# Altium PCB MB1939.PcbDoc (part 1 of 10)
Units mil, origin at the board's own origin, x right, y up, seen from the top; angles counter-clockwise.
Board outline 5910.64 x 4335.93 mil, 6 copper layers (Top Layer, l2_GND, L3_SIG, L4_VCC, L5_GND, Bottom Layer), stack 58.424 mil thick; 635 components, 489 nets, 2289 pads, 1388 vias.
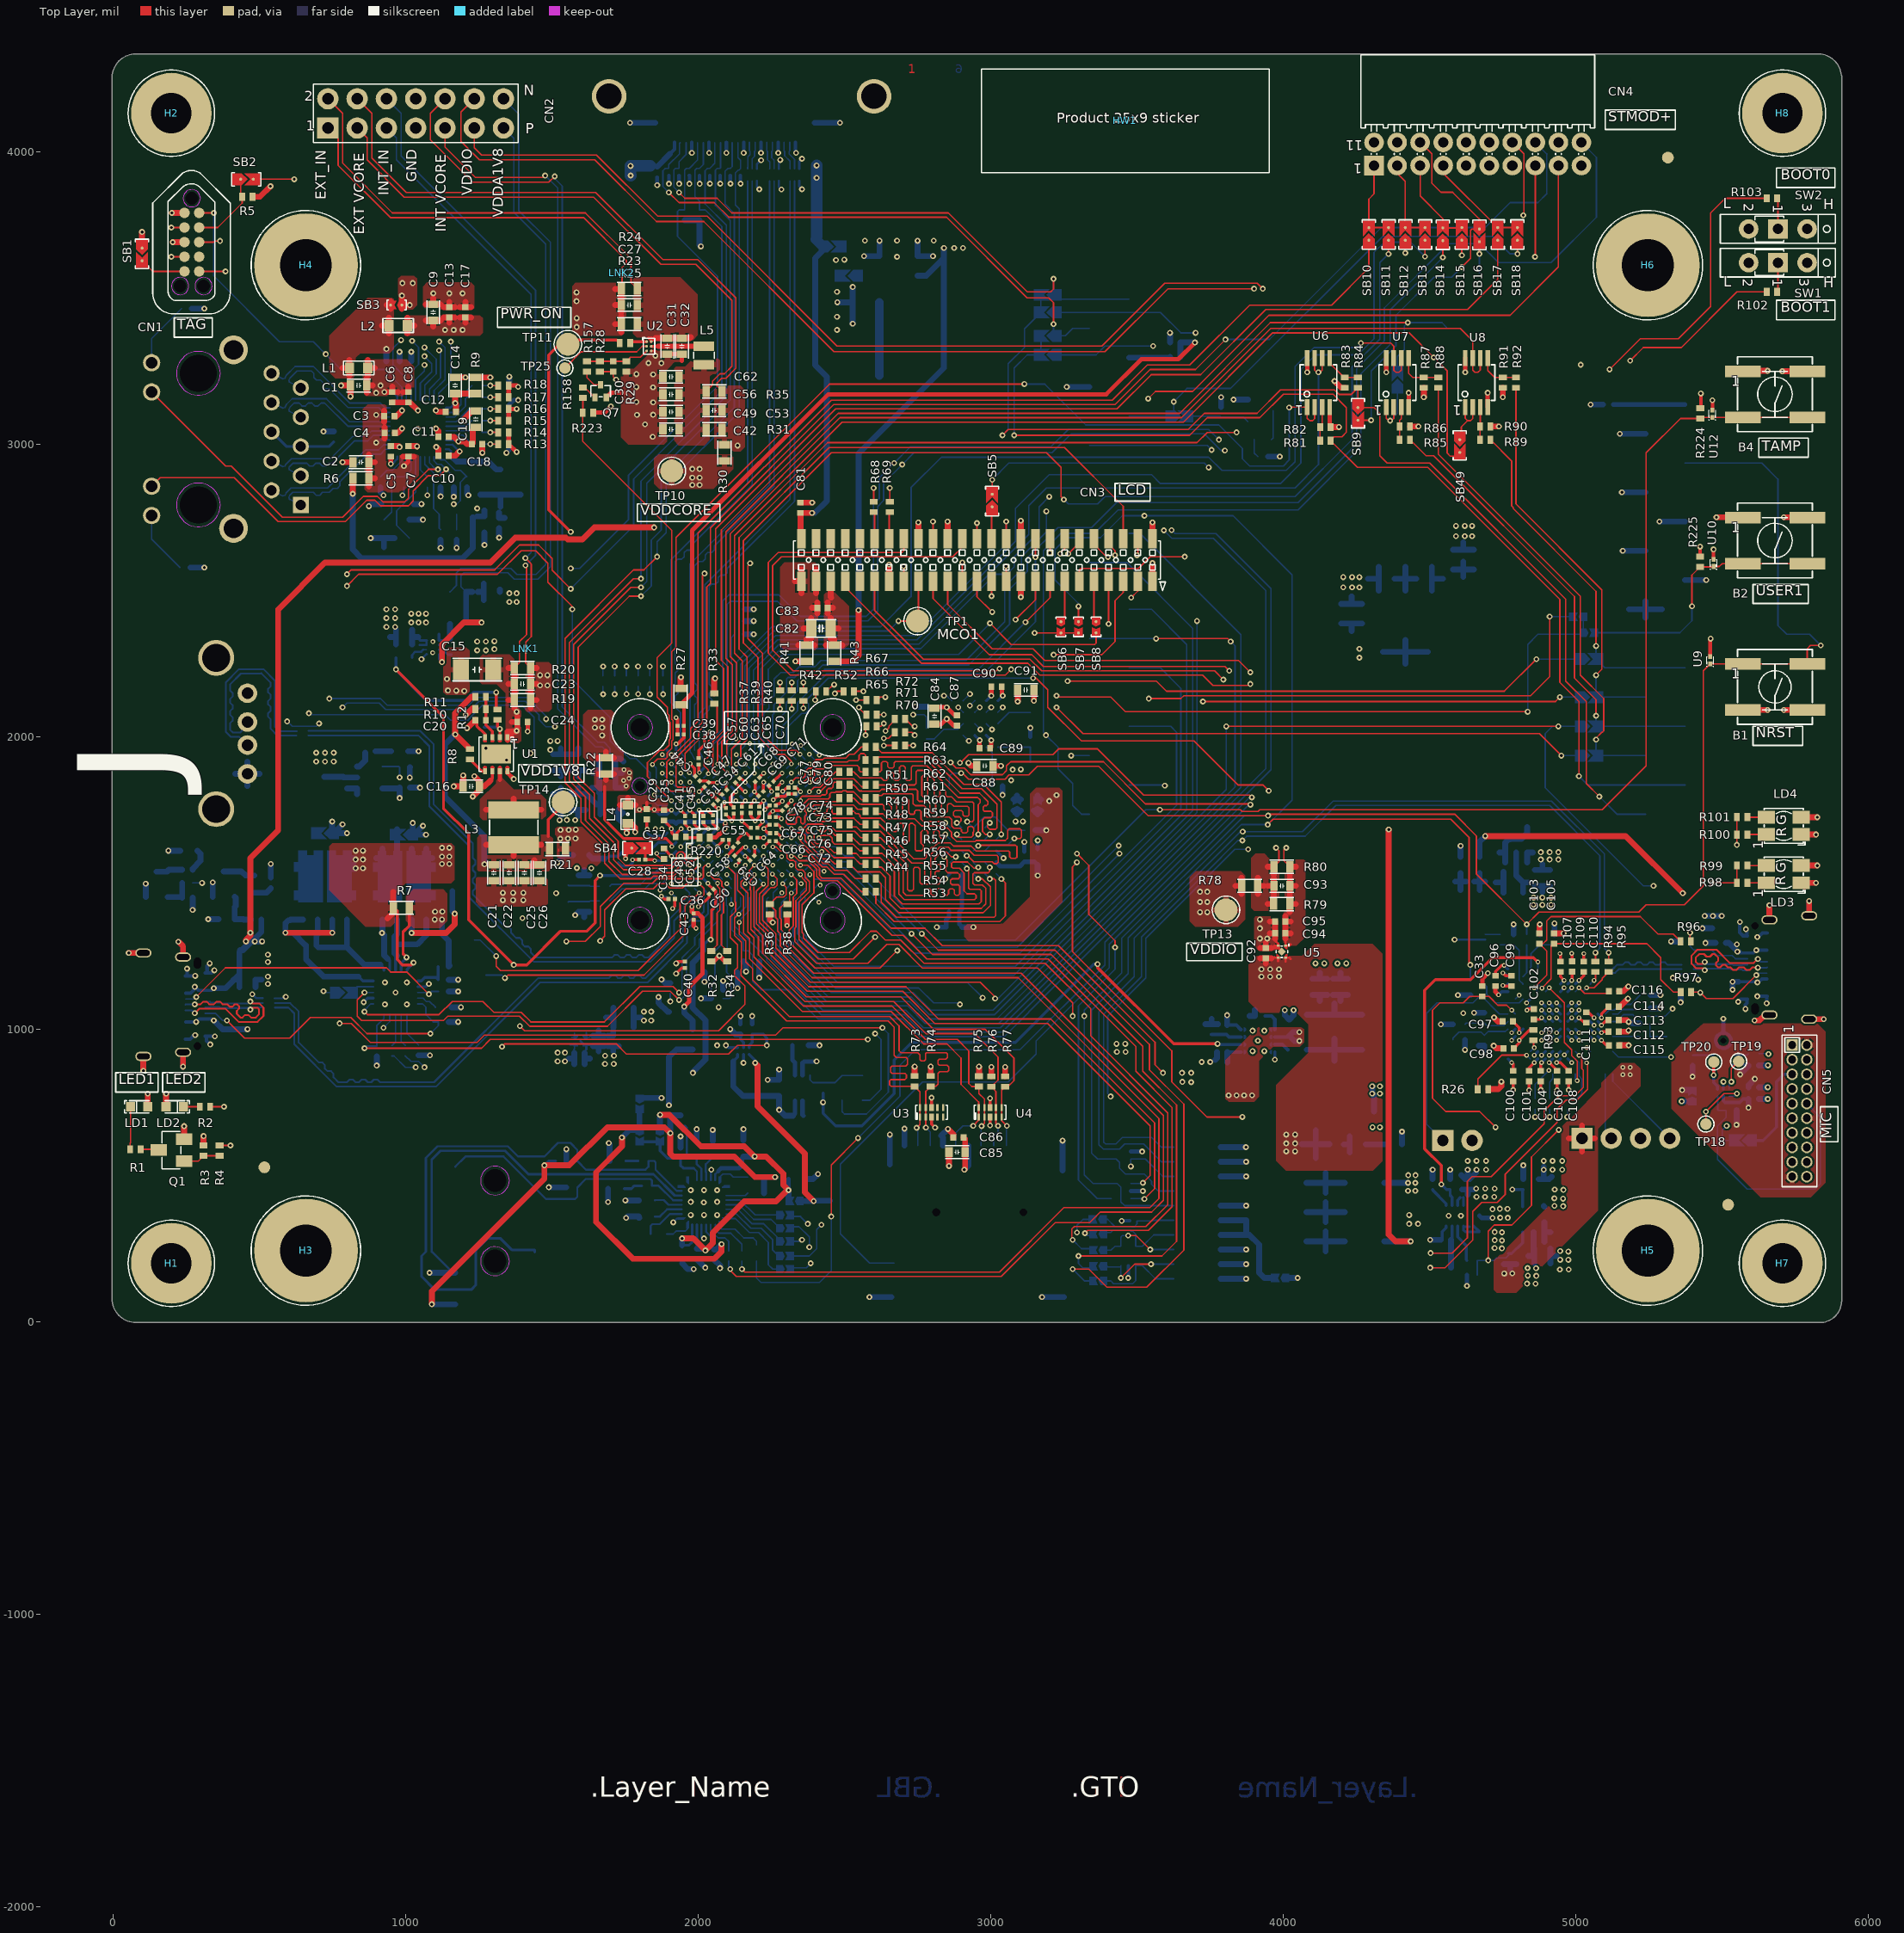
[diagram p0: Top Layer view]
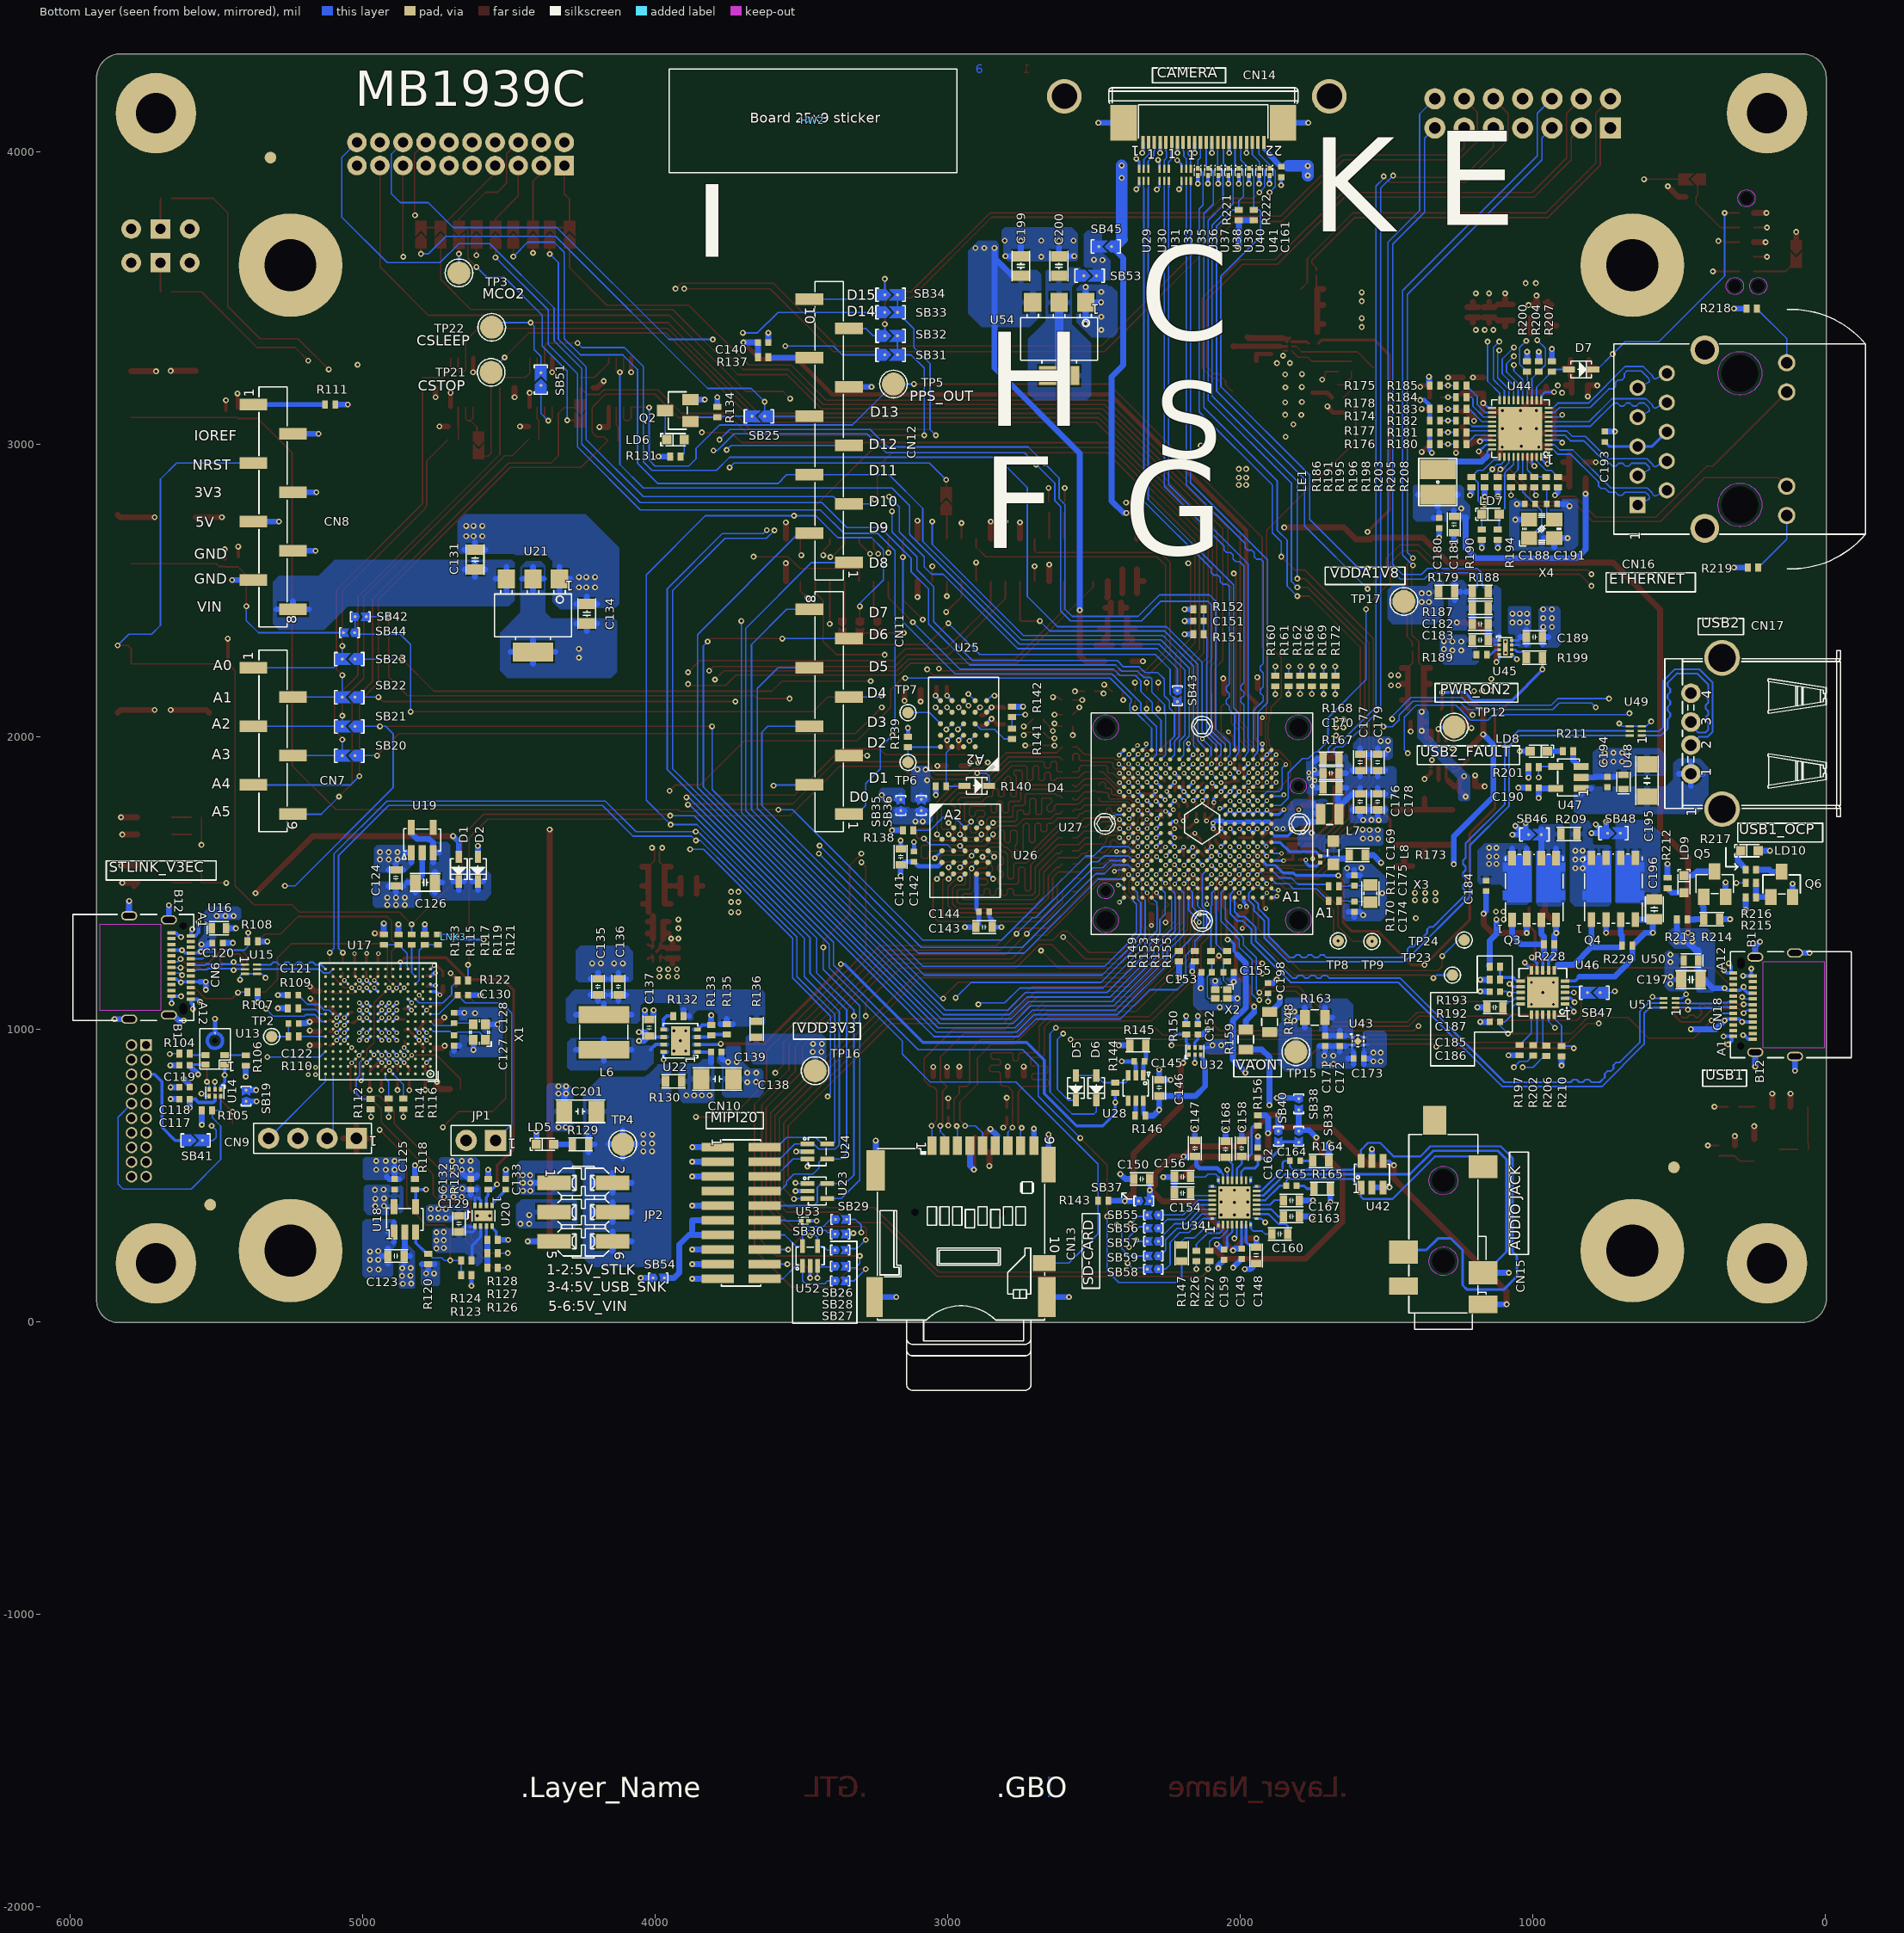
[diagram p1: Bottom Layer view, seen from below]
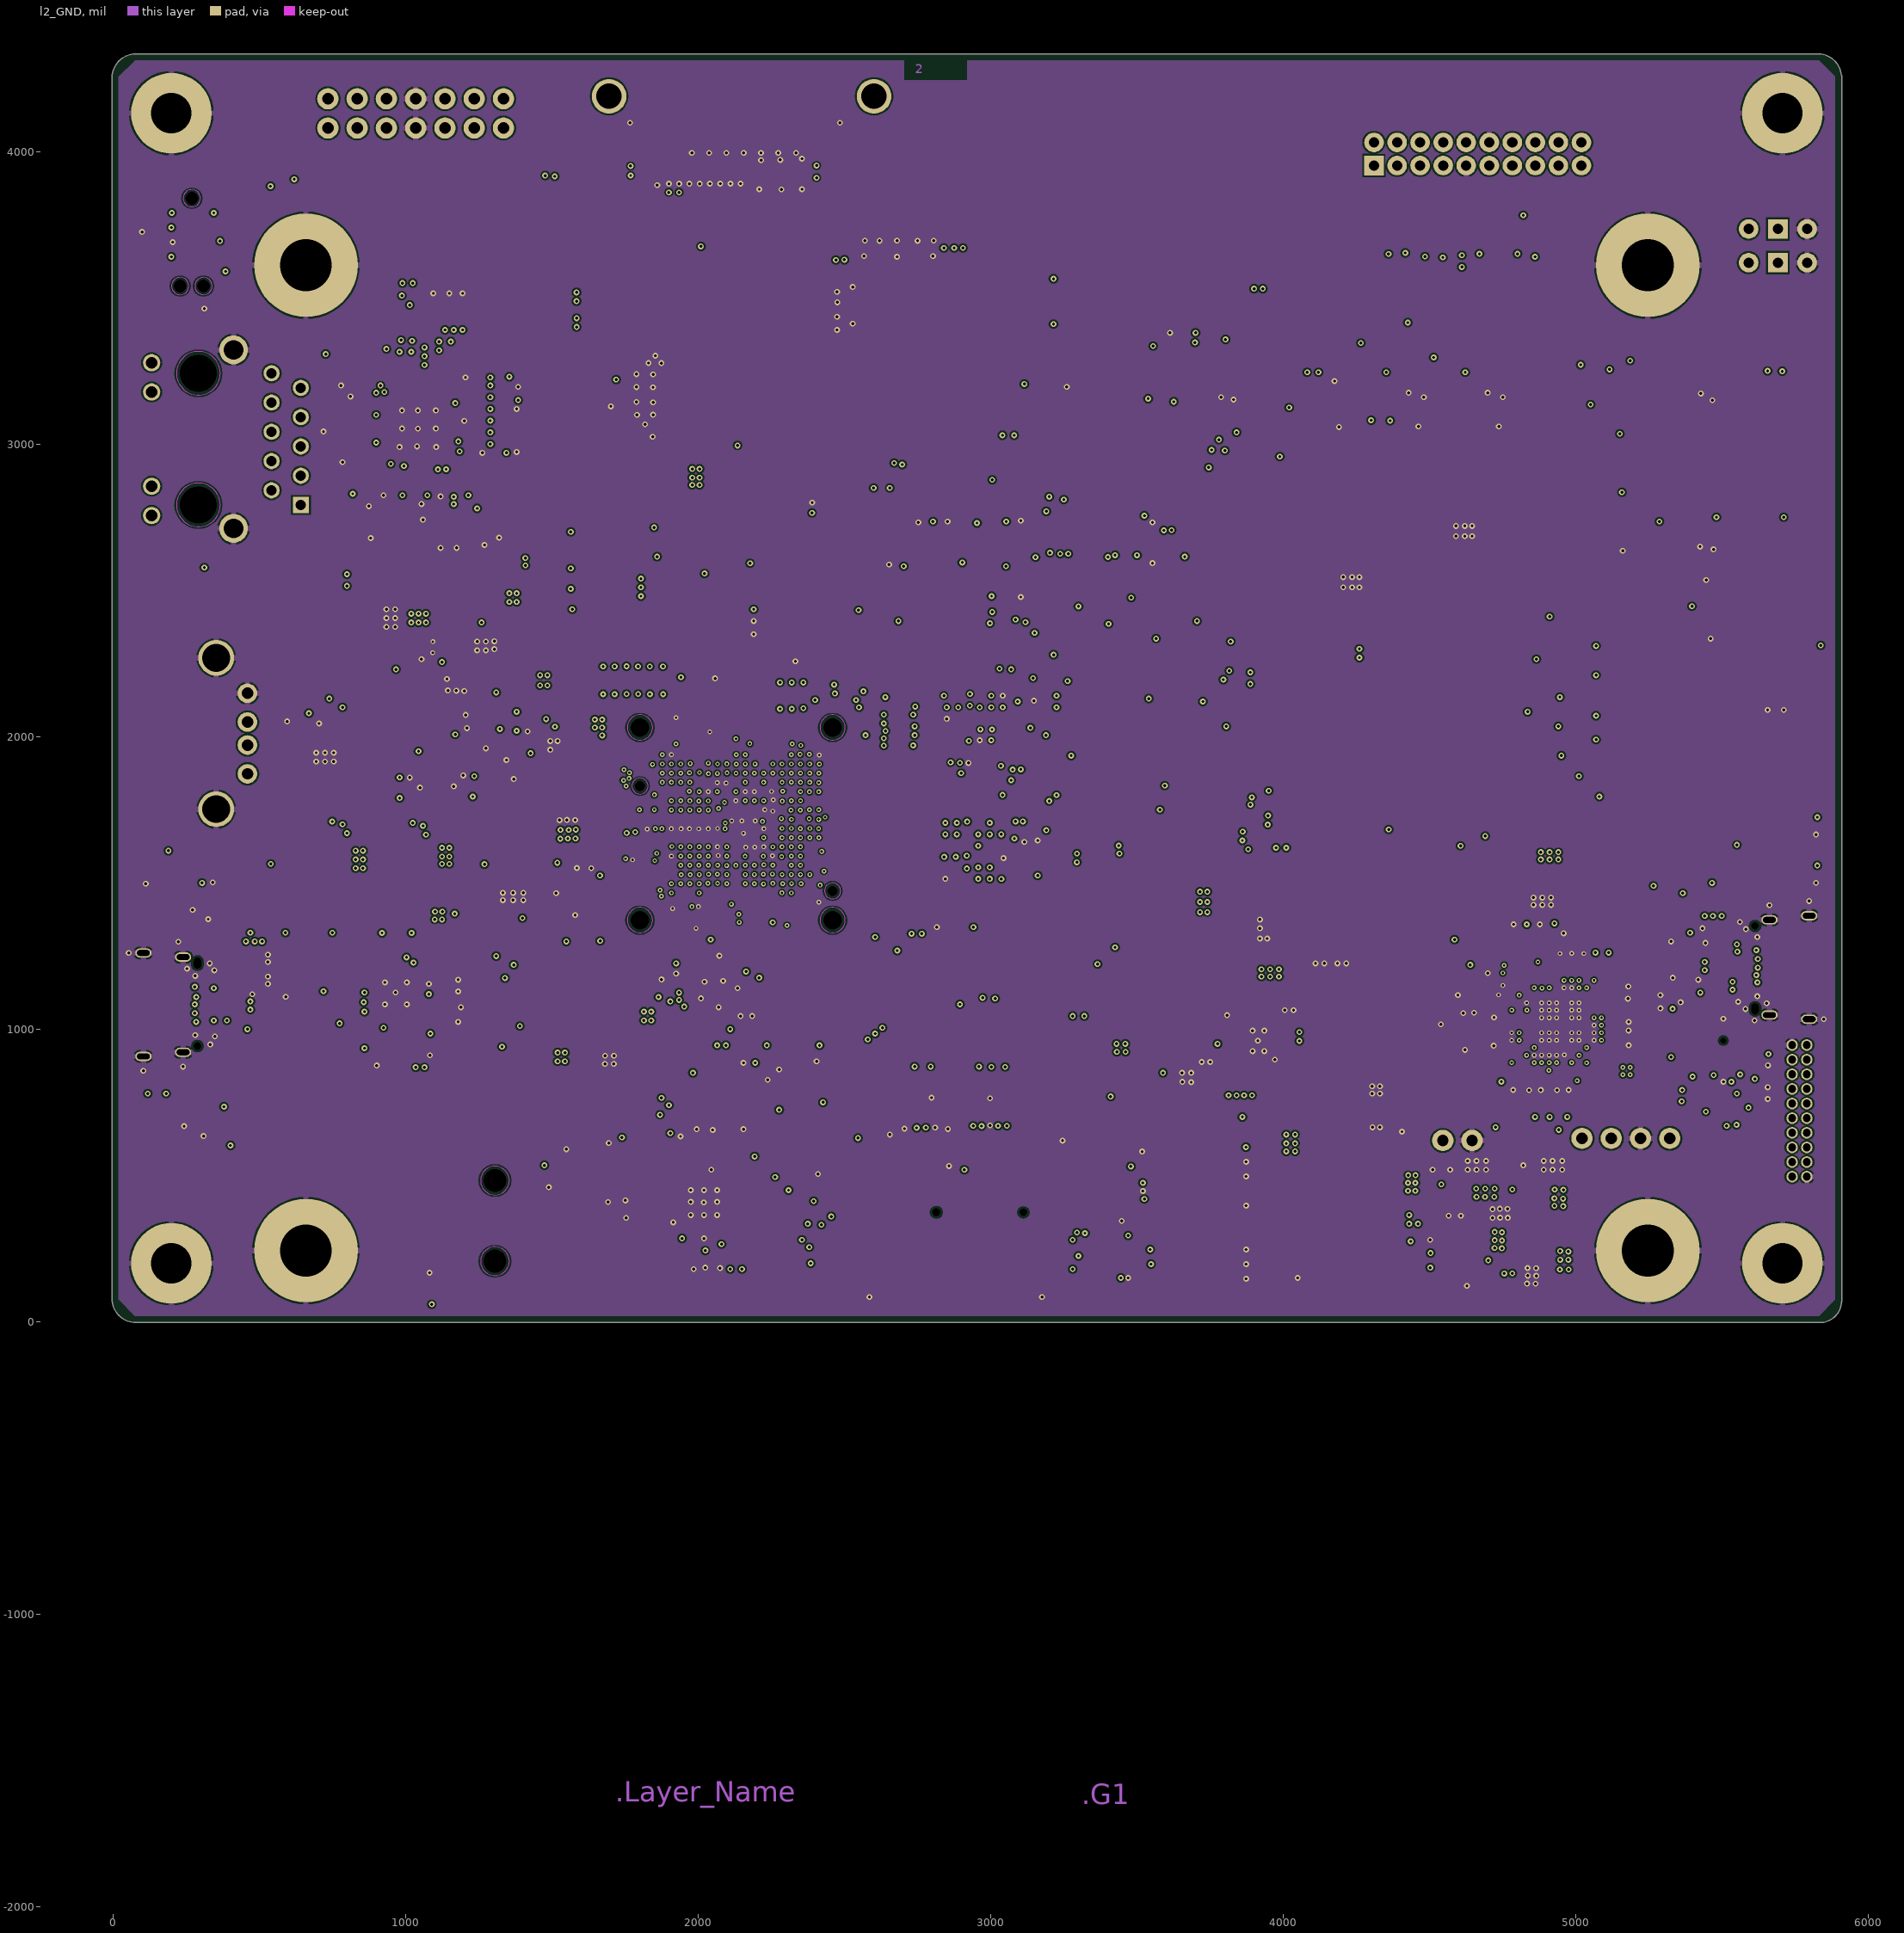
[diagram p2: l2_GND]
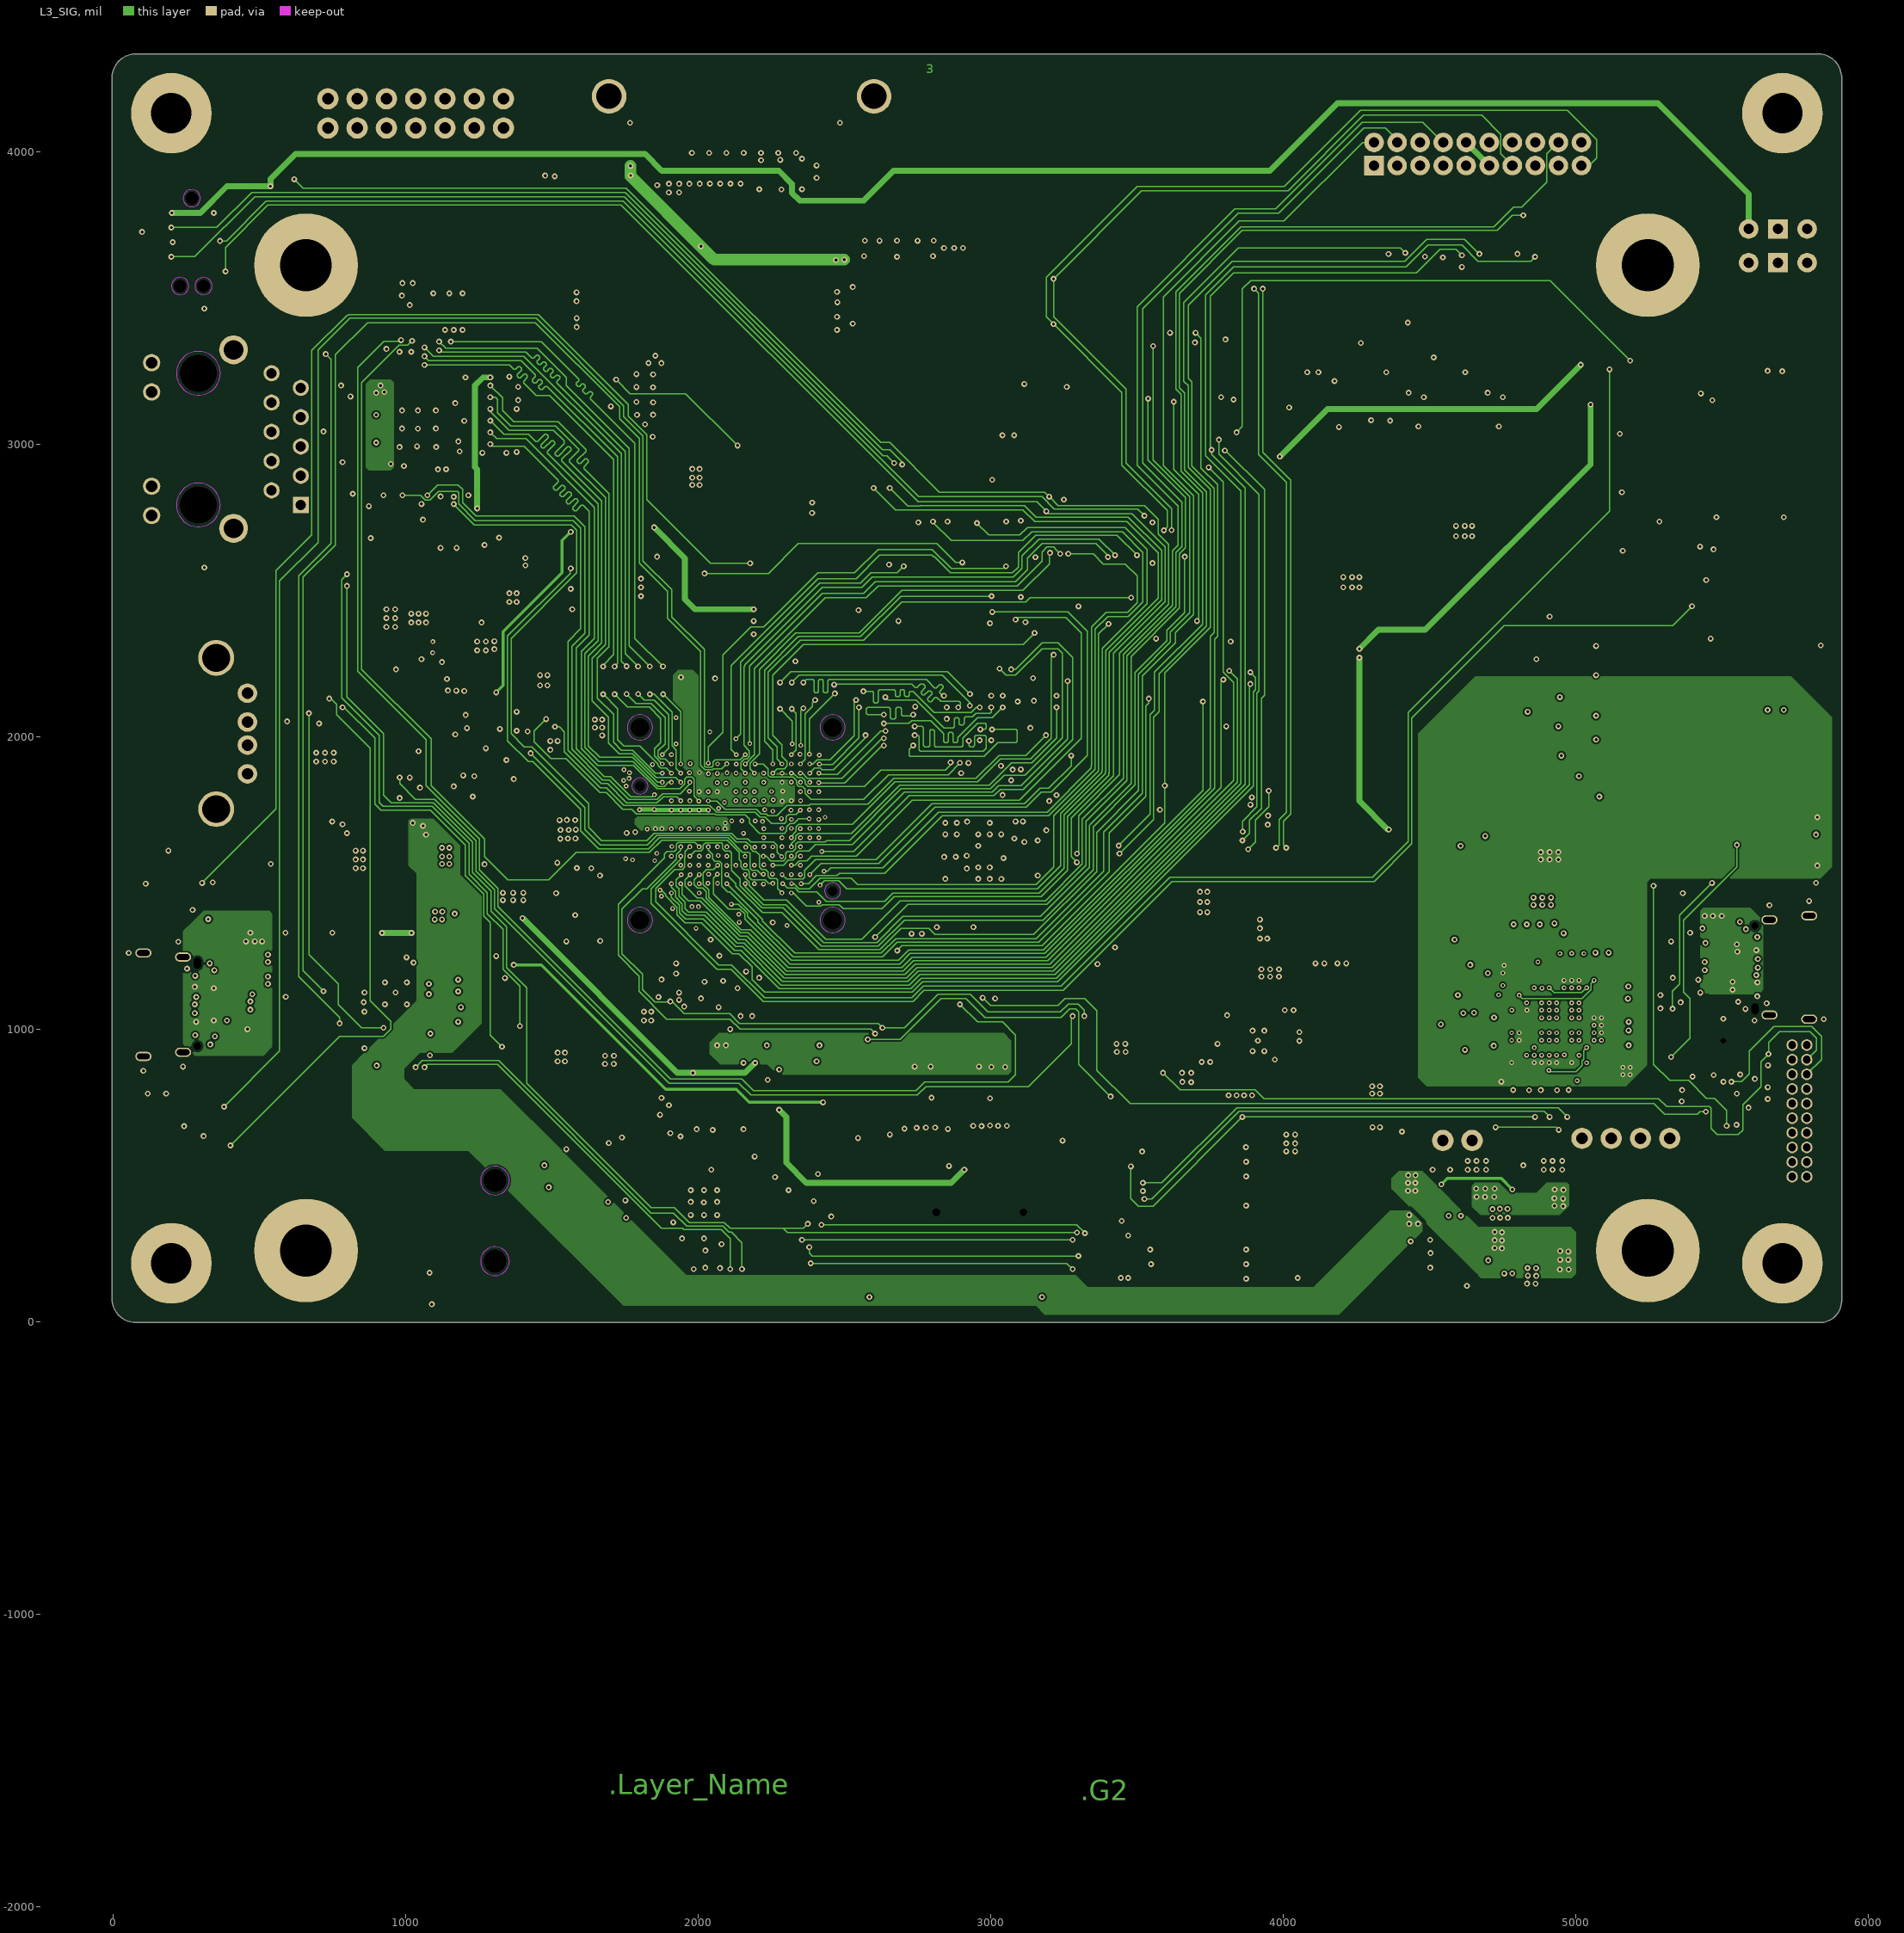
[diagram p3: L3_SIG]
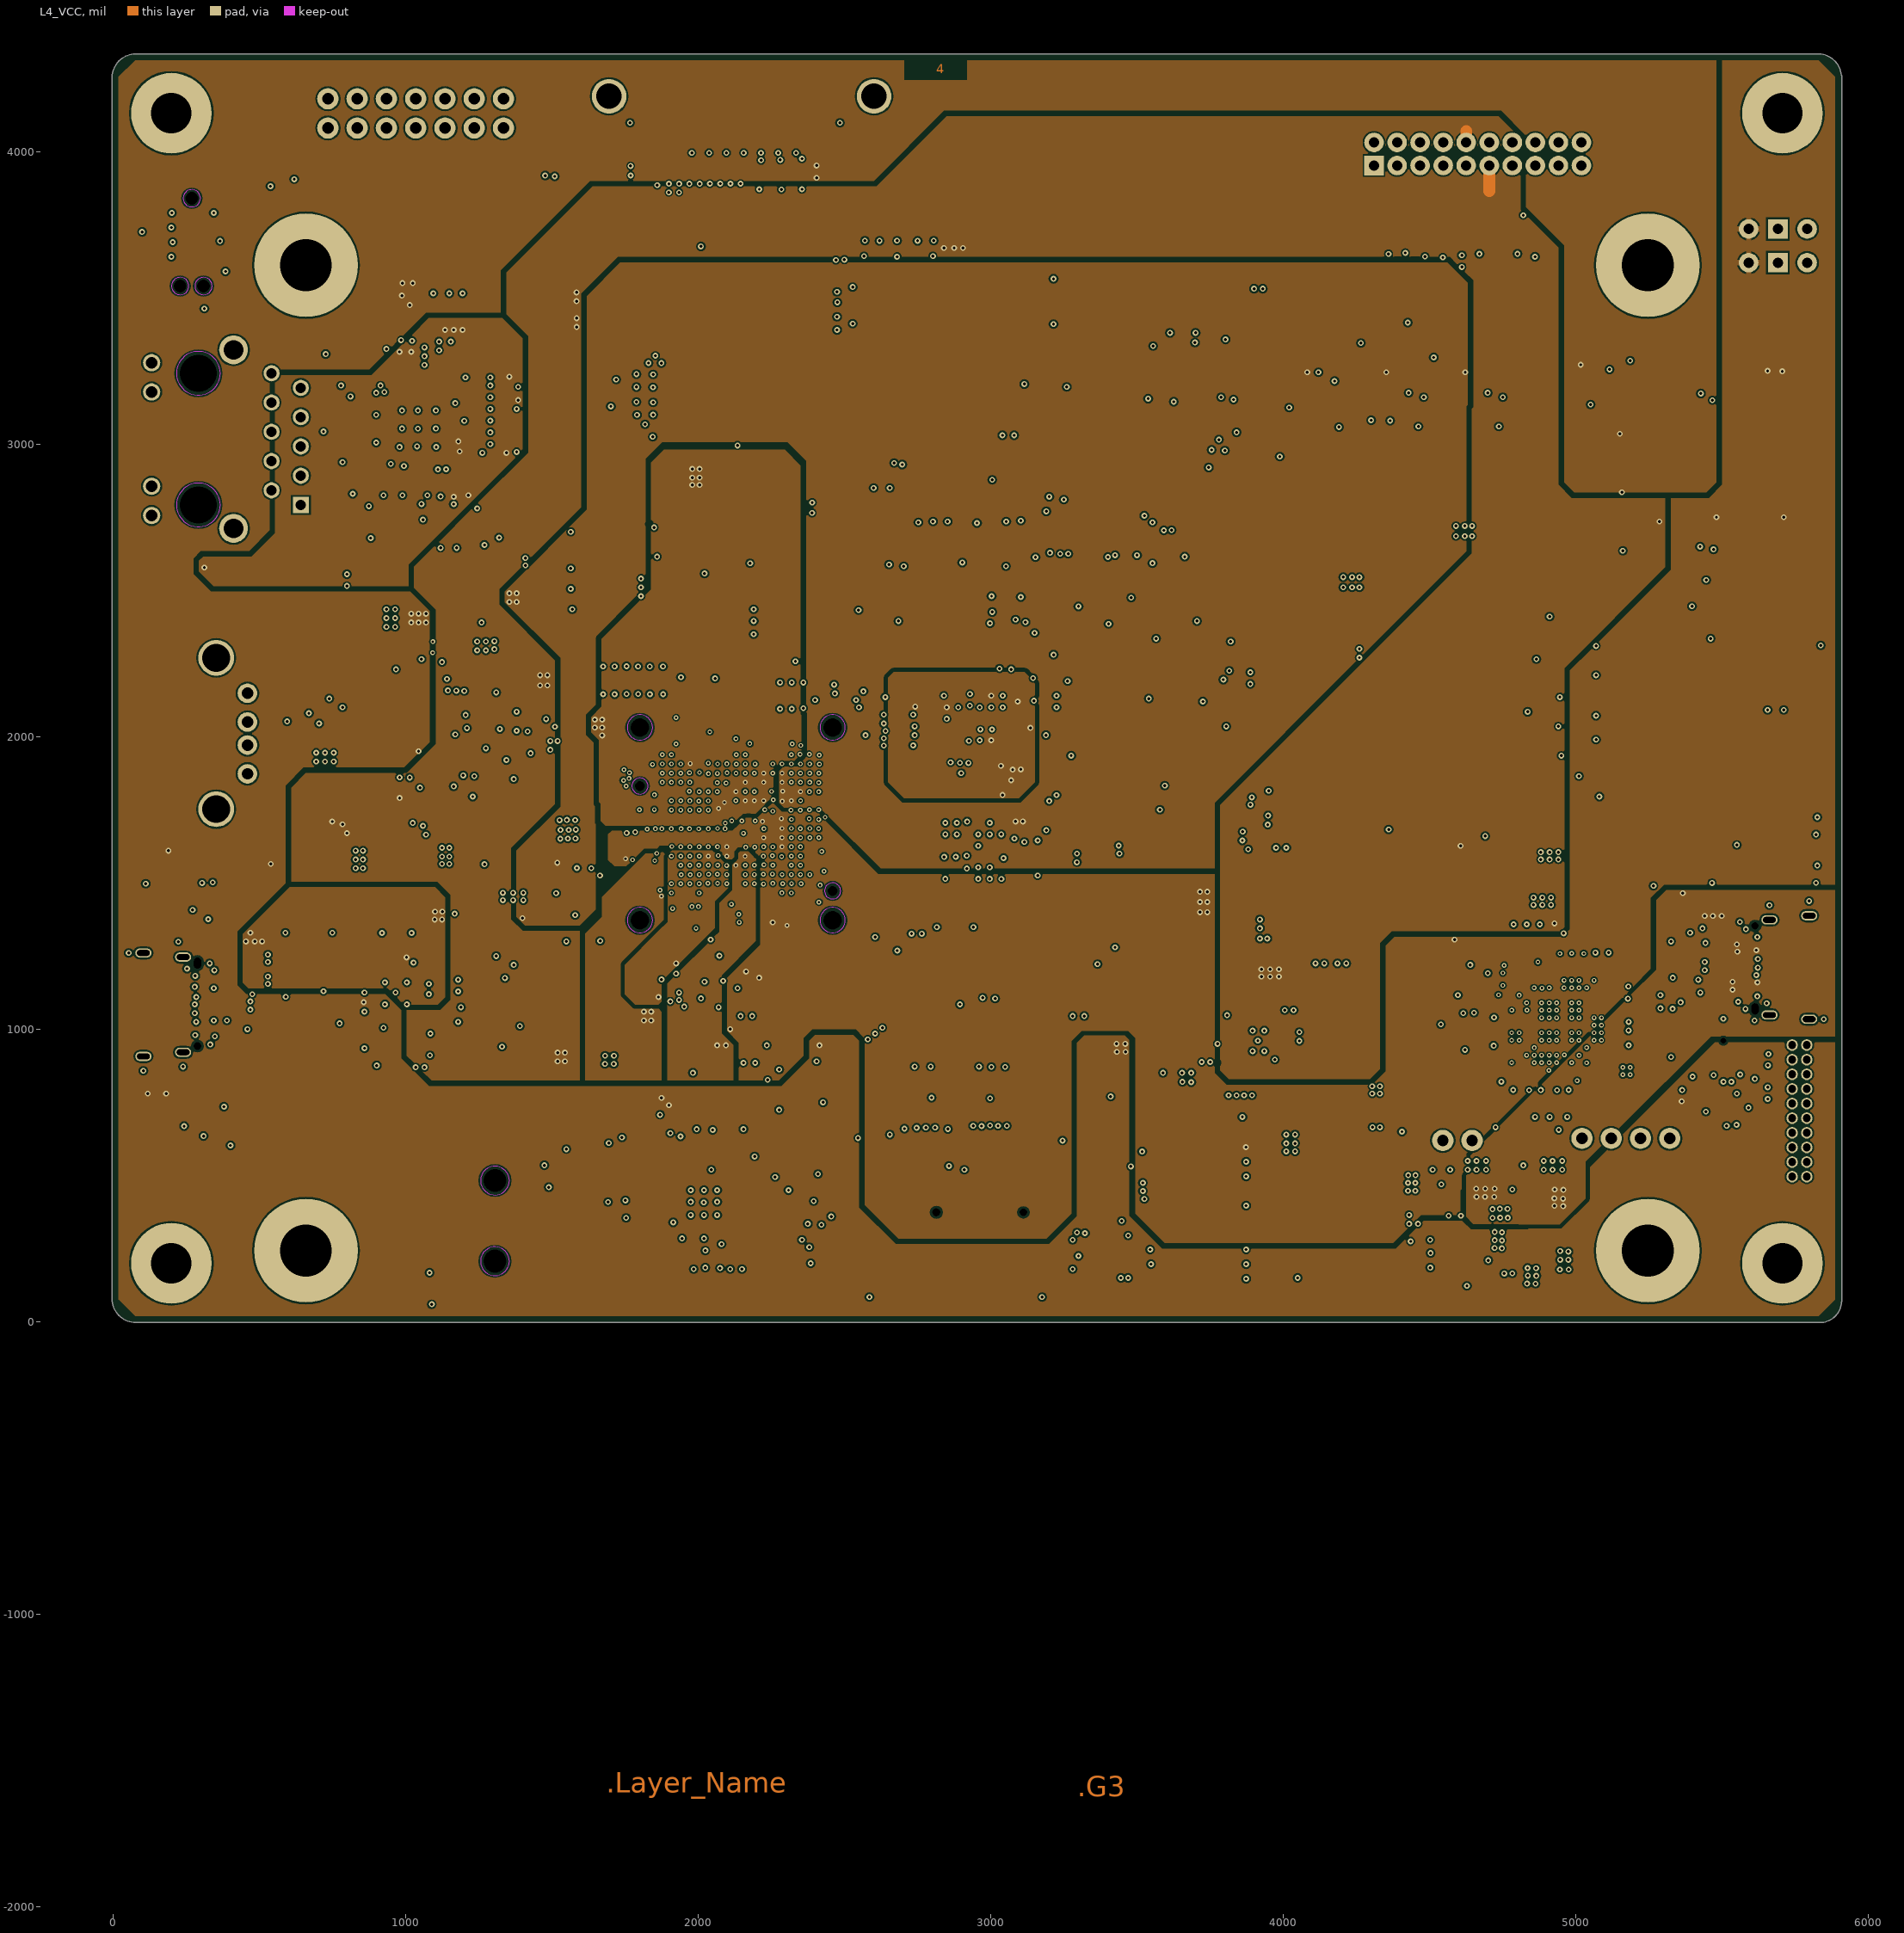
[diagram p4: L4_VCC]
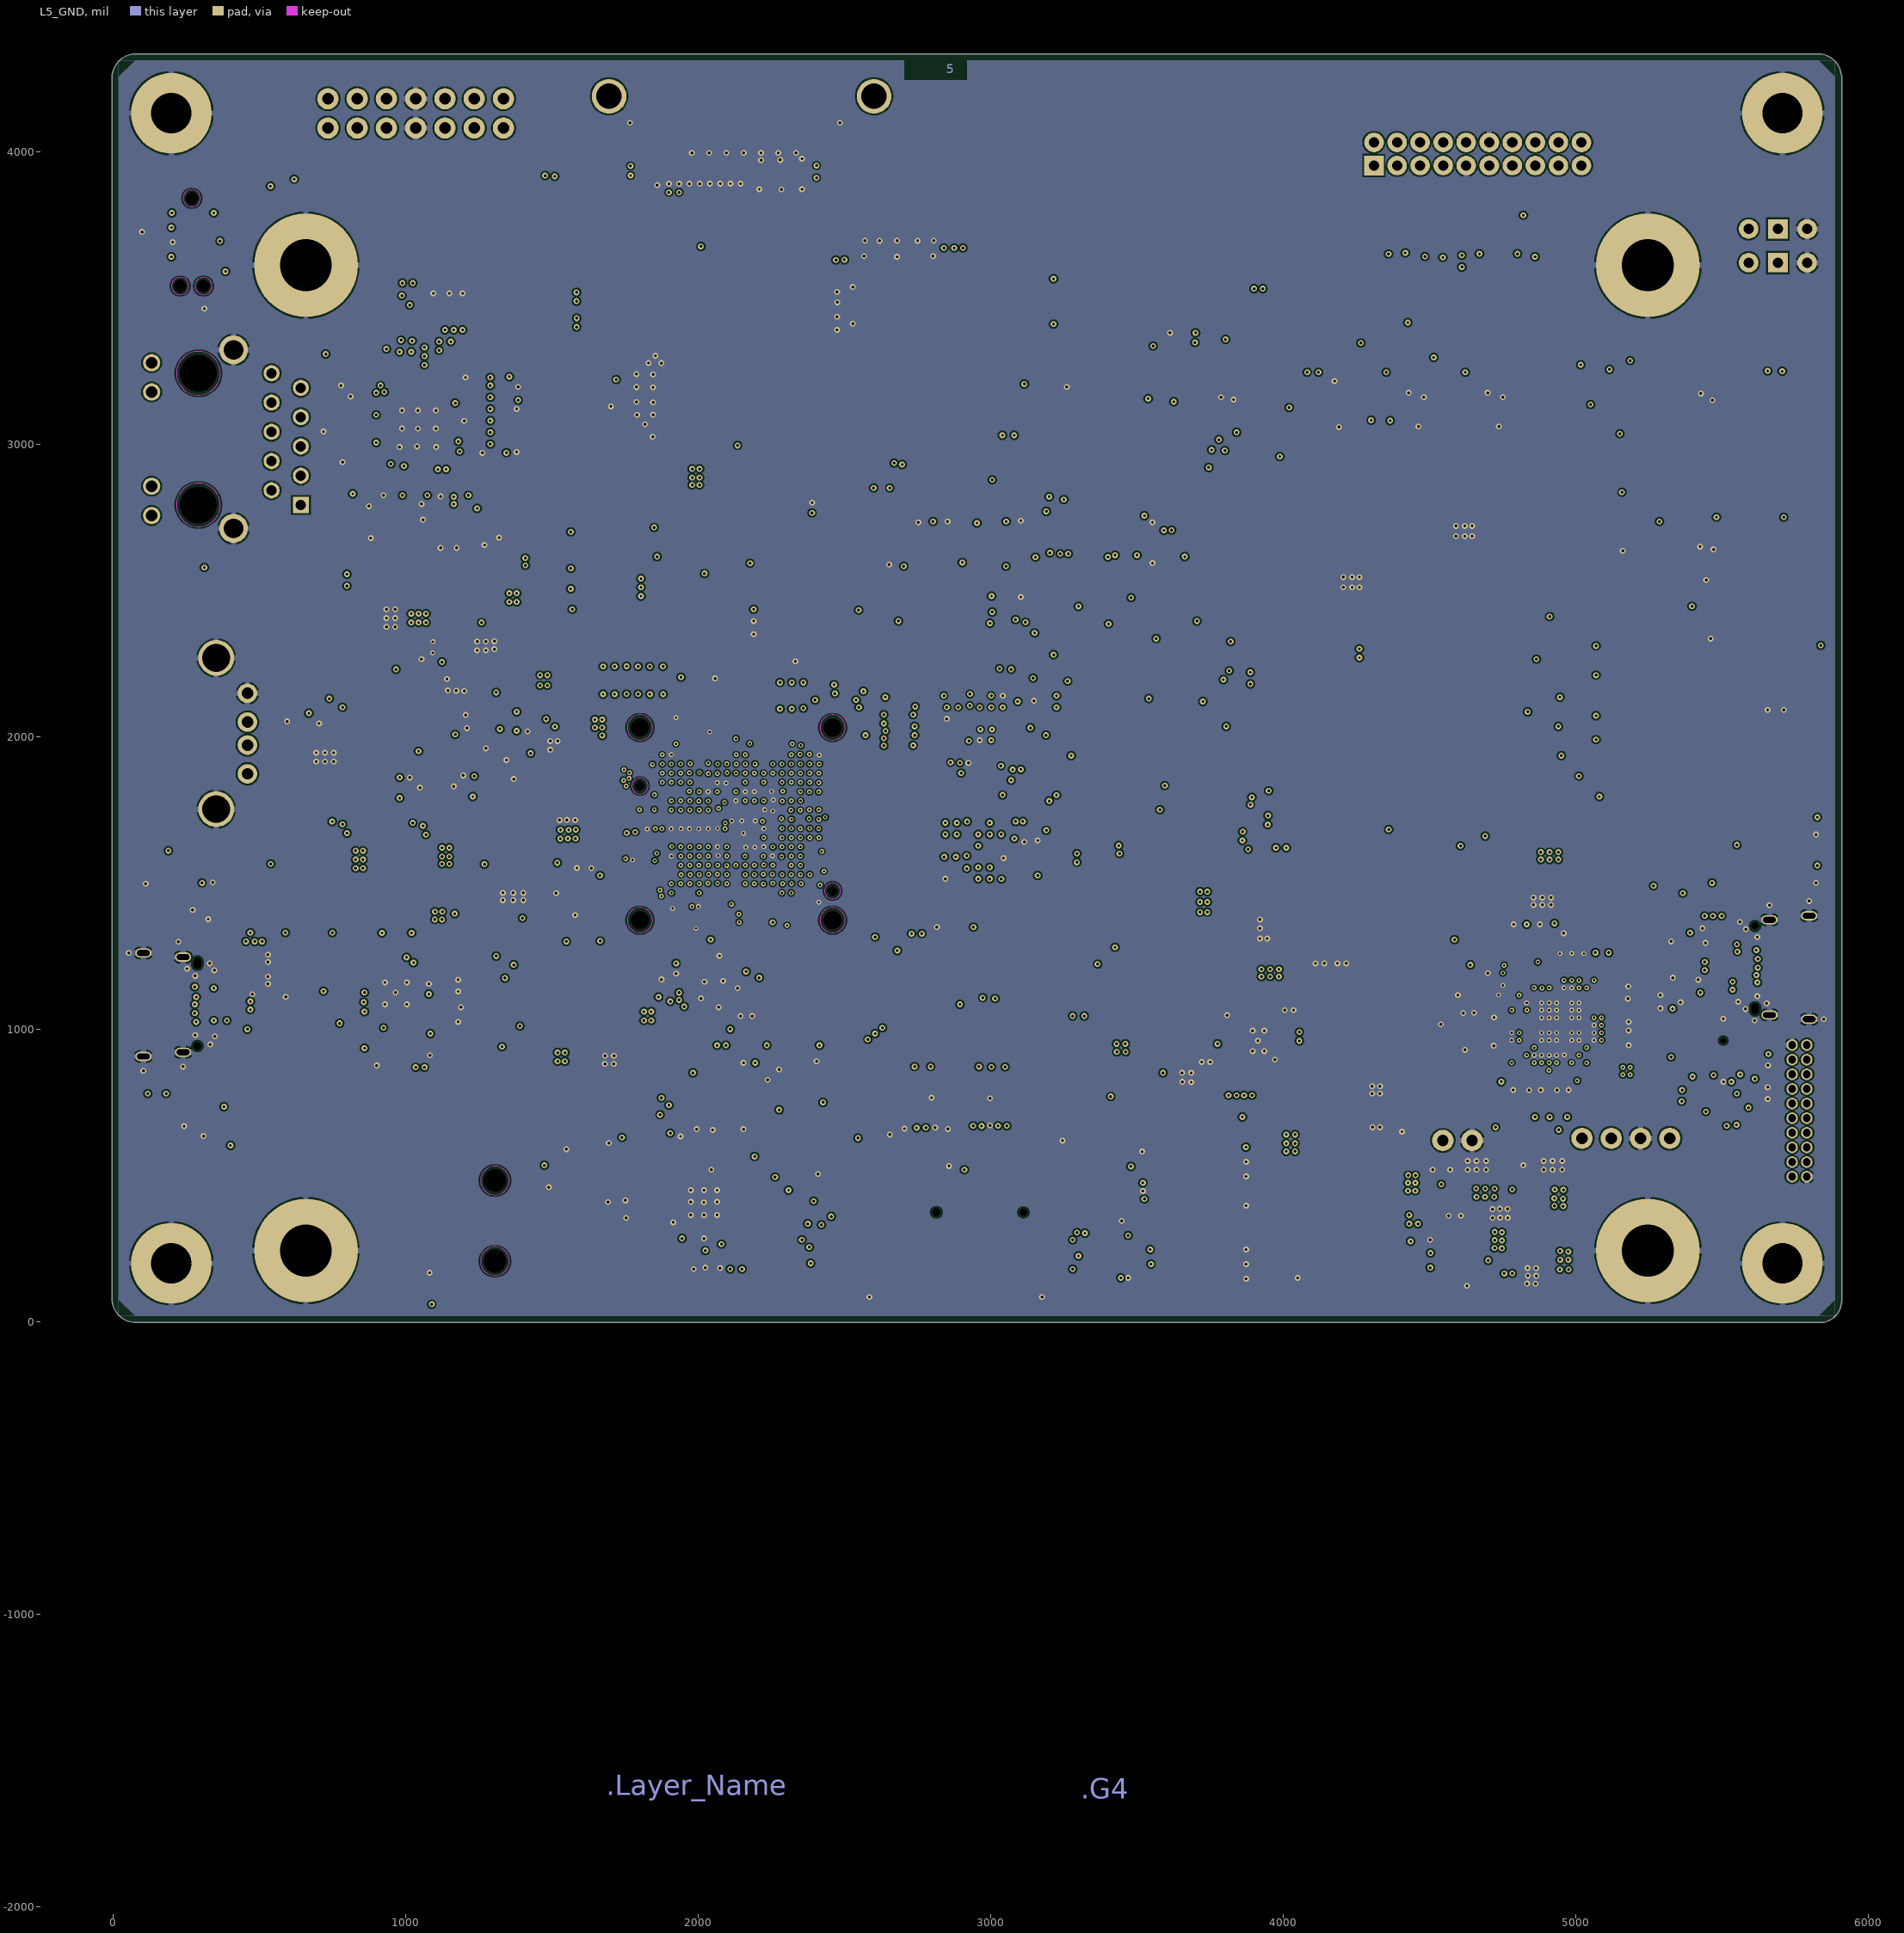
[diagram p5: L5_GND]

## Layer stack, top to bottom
Top Solder: solder mask 0.591, Solder Resist, Dk 3.5
Top Layer: signal copper 1.378
Dielectric1: core 10, FR-4, Dk 4.2
l2_GND: signal copper 1.417
Dielectric2: core 10, FR-4, Dk 4.2
L3_SIG: signal copper 1.417
Dielectric3: core 10, FR-4, Dk 4.2
L4_VCC: signal copper 1.417
Dielectric4: core 10, FR-4, Dk 4.2
L5_GND: signal copper 1.417
Dielectric5: core 10, FR-4, Dk 4.2
Bottom Layer: signal copper 1.378
Bottom Solder: solder mask 0.591, Solder Resist, Dk 3.5

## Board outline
-2.52,75.01 cw(c78.64,79.04) -2.61,79.04 cw(c-0.1,79.04) -2.52,79.74 -2.52,4251.53 cw(c-0.01,4251.7) -2.52,4251.69 cw(c78.73,4251.97) -2.52,4252.99 -2.52,4253.8 cw(c0,4253.8) -2.49,4254.13 cw(c78.73,4251.97) 76.52,4333.19 cw(c76.91,4330.71) 76.91,4333.22 5825.49,4333.22 cw(c5826.46,4330.9) 5826.46,4333.42 cw(c5826.46,4252.16) 5832.09,4333.22 5836.3,4333.22 cw(c5836.3,4330.71) 5837.96,4332.6 cw(c5826.46,4252.16) 5907.28,4260.59 cw(c5905.51,4258.8) 5908.03,4258.8 5908.03,69.7 cw(c5905.51,69.7) 5907.79,68.63 cw(c5833.81,71.52) 5833.81,-2.52 78.64,-2.52 cw(c78.64,0) 77.44,-2.21 cw(c78.64,79.04) -2.19,70.77 cw(c0,72) -2.52,72

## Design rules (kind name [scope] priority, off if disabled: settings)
Clearance Clearance_1 [HasFootprint('CON_SAMTEC_SQT-110-01-F-D-RA__STMOD+')] p1: gap=6 ignorepadtopadclearanceinfootprint=FALSE except(3.9: Arc-THPad Track-THPad; 5: Arc-SMDPad Arc-Via Arc-Text Arc-Hole Track-SMDPad Track-Via Track-Text Track-Hole SMDPad-SMDPad SMDPad-Via THPad-Via Via-Via Via-Text Via-Hole; 7.87: THPad-THPad; 8: Arc-Arc Arc-Track Track-Track SMDPad-THPad SMDPad-Text SMDPad-Hole THPad-Text THPad-Hole Fill-Text Fill-Hole Poly-Text Poly-Hole Region-Text Region-Hole Text-Text Text-Hole; 15: Fill-Fill Fill-Poly Fill-Region Poly-Poly Poly-Region Region-Region)
Clearance Clearance_U5 [HasFootprint('ICC_VFDFPN8-EPAD_3X3_P065')] p2: gap=6 ignorepadtopadclearanceinfootprint=FALSE except(5: Arc-SMDPad Arc-THPad Arc-Via Arc-Text Arc-Hole Track-SMDPad Track-THPad Track-Via Track-Text Track-Hole SMDPad-SMDPad SMDPad-Via THPad-Via Via-Via Via-Text Via-Hole; 8: Arc-Arc Arc-Track Track-Track SMDPad-THPad SMDPad-Text SMDPad-Hole THPad-THPad THPad-Text THPad-Hole Fill-Text Fill-Hole Poly-Text Poly-Hole Region-Text Region-Hole Text-Text Text-Hole; 11: Fill-Fill Fill-Poly Fill-Region Poly-Poly Poly-Region Region-Region)
Clearance Clearance_LINK [HasFootprint('LINK200')] p3: gap=3 ignorepadtopadclearanceinfootprint=FALSE except(0: SMDPad-SMDPad)
Clearance Clearance_SB [HasFootprint('SOLDER-BRIDGE_R0603-0R','SOLDER-BRIDGE_R0402-0R')] p4: gap=6 ignorepadtopadclearanceinfootprint=FALSE
Clearance Clearance_Room [WithinRoom('Room_External_SMPS','Room_External_SMPS','Room_FLASH','Room_MCU','Room_STLINK','Room_CAMERA')] p5: gap=4 ignorepadtopadclearanceinfootprint=FALSE except(5: Via-Fill Via-Poly Via-Region; 6: Arc-Fill Arc-Poly Arc-Region Track-Fill Track-Poly Track-Region SMDPad-Fill SMDPad-Poly SMDPad-Region THPad-Fill THPad-Poly THPad-Region; 15: Fill-Fill Fill-Poly Fill-Region Poly-Poly Poly-Region Region-Region)
Clearance Clearance_90ohm [InNetClass('90OHM')] p6: gap=5 ignorepadtopadclearanceinfootprint=FALSE except(6: Arc-Fill Arc-Poly Arc-Region Track-Fill Track-Poly Track-Region SMDPad-Fill SMDPad-Poly SMDPad-Region THPad-Fill THPad-Poly THPad-Region Via-Fill Via-Poly Via-Region; 8.9: Arc-Arc Arc-Track Track-Track; 20: Fill-Fill Fill-Poly Fill-Region Poly-Poly Poly-Region Region-Region)
Clearance Clearance_100ohm [InNetClass('100OHM')] p7: gap=5 ignorepadtopadclearanceinfootprint=FALSE except(6: Arc-Fill Arc-Poly Arc-Region Track-Fill Track-Poly Track-Region SMDPad-Fill SMDPad-Poly SMDPad-Region THPad-Fill THPad-Poly THPad-Region Via-Fill Via-Poly Via-Region; 9.9: Arc-Arc Arc-Track Track-Track; 20: Fill-Fill Fill-Poly Fill-Region Poly-Poly Poly-Region Region-Region)
Clearance [All] p8: gap=6 ignorepadtopadclearanceinfootprint=FALSE except(5: Arc-SMDPad Arc-THPad Arc-Via Arc-Text Arc-Hole Track-SMDPad Track-THPad Track-Via Track-Text Track-Hole SMDPad-SMDPad SMDPad-Via THPad-Via Via-Via Via-Text Via-Hole; 7.87: THPad-THPad; 8: Arc-Arc Arc-Track Track-Track SMDPad-THPad SMDPad-Text SMDPad-Hole THPad-Text THPad-Hole Fill-Text Fill-Hole Poly-Text Poly-Hole Region-Text Region-Hole Text-Text Text-Hole; 15: Fill-Fill Fill-Poly Fill-Region Poly-Poly Poly-Region Region-Region)
ComponentClearance [All] p1: gap=7.87 collisioncheckmode=3 verticalgap=7.87 showdistances=FALSE
DiffPairsRouting DiffPairsRouting_100ohm [InDifferentialPair('No Differential Pair')] p1: maxlimit=10.9 minlimit=4 mostfreqgap=10.9 toplayer_maxgap=9.9 toplayer_prefgap=9.9 toplayer_minwidth=4 toplayer_maxwidth=5.1 toplayer_prefwidth=5.1 midlayer1_maxgap=9.9 midlayer1_prefgap=9.9 midlayer1_minwidth=4 midlayer1_maxwidth=5.1 midlayer1_prefwidth=5.1 midlayer2_minwidth=4 midlayer2_maxwidth=4.1 midlayer2_prefwidth=4.1 midlayer3_maxgap=9.9 midlayer3_prefgap=9.9 midlayer3_minwidth=4 midlayer3_maxwidth=5.1 midlayer3_prefwidth=5.1 midlayer4_maxgap=9.9 midlayer4_prefgap=9.9 midlayer4_minwidth=4 midlayer4_maxwidth=5.1 midlayer4_prefwidth=5.1 bottomlayer_maxgap=9.9 bottomlayer_prefgap=9.9 bottomlayer_minwidth=4 bottomlayer_maxwidth=5.1 bottomlayer_prefwidth=5.1 maxuncoupledlength=500
DiffPairsRouting DiffPairsRouting_90ohm [All] p2: maxlimit=9.9 minlimit=4 mostfreqgap=9.9 toplayer_maxgap=8.9 toplayer_prefgap=8.9 toplayer_minwidth=4 toplayer_maxwidth=6.1 toplayer_prefwidth=6.1 midlayer1_maxgap=8.9 midlayer1_prefgap=8.9 midlayer1_minwidth=4 midlayer1_maxwidth=6.1 midlayer1_prefwidth=6.1 midlayer2_minwidth=4 midlayer2_maxwidth=5.1 midlayer2_prefwidth=5.1 midlayer3_maxgap=8.9 midlayer3_prefgap=8.9 midlayer3_minwidth=4 midlayer3_maxwidth=6.1 midlayer3_prefwidth=6.1 midlayer4_maxgap=8.9 midlayer4_prefgap=8.9 midlayer4_minwidth=4 midlayer4_maxwidth=6.1 midlayer4_prefwidth=6.1 bottomlayer_maxgap=8.9 bottomlayer_prefgap=8.9 bottomlayer_minwidth=4 bottomlayer_maxwidth=6.1 bottomlayer_prefwidth=6.1 maxuncoupledlength=500
HoleSize [All] p1: absolutevalues=TRUE maxlimit=393.7 minlimit=1 maxpercent=80.000 minpercent=20.000
MatchedLengths "Schematic Matched Net Lengths_30" [InNet('HEXASPI_NCS')] p1: tolerance=1000 checknetsindiffpair=FALSE checkdiffpairvsdiffpair=TRUE checkxsignals=TRUE checkothers=TRUE
MatchedLengths "Schematic Matched Net Lengths_29" [InNet('OCTOSPI_NCS')] p2: tolerance=1000 checknetsindiffpair=FALSE checkdiffpairvsdiffpair=TRUE checkxsignals=TRUE checkothers=TRUE
MatchedLengths "Schematic Matched Net Lengths_28" [InNet('HEXASPI_IO4')] p3: tolerance=20 checknetsindiffpair=FALSE checkdiffpairvsdiffpair=TRUE checkxsignals=TRUE checkothers=TRUE
MatchedLengths "Schematic Matched Net Lengths_27" [InNet('HEXASPI_IO8')] p4: tolerance=20 checknetsindiffpair=FALSE checkdiffpairvsdiffpair=TRUE checkxsignals=TRUE checkothers=TRUE
MatchedLengths "Schematic Matched Net Lengths_26" [InNet('HEXASPI_IO5')] p5: tolerance=20 checknetsindiffpair=FALSE checkdiffpairvsdiffpair=TRUE checkxsignals=TRUE checkothers=TRUE
MatchedLengths "Schematic Matched Net Lengths_25" [InNet('OCTOSPI_IO5')] p6: tolerance=20 checknetsindiffpair=FALSE checkdiffpairvsdiffpair=TRUE checkxsignals=TRUE checkothers=TRUE
MatchedLengths "Schematic Matched Net Lengths_24" [InNet('OCTOSPI_IO6')] p7: tolerance=20 checknetsindiffpair=FALSE checkdiffpairvsdiffpair=TRUE checkxsignals=TRUE checkothers=TRUE
MatchedLengths "Schematic Matched Net Lengths_23" [InNet('HEXASPI_DQS1')] p8: tolerance=20 checknetsindiffpair=FALSE checkdiffpairvsdiffpair=TRUE checkxsignals=TRUE checkothers=TRUE
MatchedLengths "Schematic Matched Net Lengths_22" [InNet('HEXASPI_IO0')] p9: tolerance=20 checknetsindiffpair=FALSE checkdiffpairvsdiffpair=TRUE checkxsignals=TRUE checkothers=TRUE
MatchedLengths "Schematic Matched Net Lengths_21" [InNet('HEXASPI_CLK')] p10: tolerance=20 checknetsindiffpair=FALSE checkdiffpairvsdiffpair=TRUE checkxsignals=TRUE checkothers=TRUE
MatchedLengths "Schematic Matched Net Lengths_20" [InNet('HEXASPI_IO3')] p11: tolerance=20 checknetsindiffpair=FALSE checkdiffpairvsdiffpair=TRUE checkxsignals=TRUE checkothers=TRUE
MatchedLengths "Schematic Matched Net Lengths_19" [InNet('OCTOSPI_IO0')] p12: tolerance=20 checknetsindiffpair=FALSE checkdiffpairvsdiffpair=TRUE checkxsignals=TRUE checkothers=TRUE
MatchedLengths "Schematic Matched Net Lengths_18" [InNet('HEXASPI_IO12')] p13: tolerance=20 checknetsindiffpair=FALSE checkdiffpairvsdiffpair=TRUE checkxsignals=TRUE checkothers=TRUE
MatchedLengths "Schematic Matched Net Lengths_17" [InNet('HEXASPI_IO14')] p14: tolerance=20 checknetsindiffpair=FALSE checkdiffpairvsdiffpair=TRUE checkxsignals=TRUE checkothers=TRUE
MatchedLengths "Schematic Matched Net Lengths_16" [InNet('HEXASPI_IO9')] p15: tolerance=20 checknetsindiffpair=FALSE checkdiffpairvsdiffpair=TRUE checkxsignals=TRUE checkothers=TRUE
MatchedLengths "Schematic Matched Net Lengths_15" [InNet('OCTOSPI_IO7')] p16: tolerance=20 checknetsindiffpair=FALSE checkdiffpairvsdiffpair=TRUE checkxsignals=TRUE checkothers=TRUE
MatchedLengths "Schematic Matched Net Lengths_14" [InNet('OCTOSPI_IO1')] p17: tolerance=20 checknetsindiffpair=FALSE checkdiffpairvsdiffpair=TRUE checkxsignals=TRUE checkothers=TRUE
MatchedLengths "Schematic Matched Net Lengths_13" [InNet('HEXASPI_IO11')] p18: tolerance=20 checknetsindiffpair=FALSE checkdiffpairvsdiffpair=TRUE checkxsignals=TRUE checkothers=TRUE
MatchedLengths "Schematic Matched Net Lengths_12" [InNet('OCTOSPI_IO4')] p19: tolerance=20 checknetsindiffpair=FALSE checkdiffpairvsdiffpair=TRUE checkxsignals=TRUE checkothers=TRUE
MatchedLengths "Schematic Matched Net Lengths_11" [InNet('OCTOSPI_IO2')] p20: tolerance=20 checknetsindiffpair=FALSE checkdiffpairvsdiffpair=TRUE checkxsignals=TRUE checkothers=TRUE
MatchedLengths "Schematic Matched Net Lengths_10" [InNet('OCTOSPI_IO3')] p21: tolerance=20 checknetsindiffpair=FALSE checkdiffpairvsdiffpair=TRUE checkxsignals=TRUE checkothers=TRUE
MatchedLengths "Schematic Matched Net Lengths_9" [InNet('HEXASPI_IO15')] p22: tolerance=20 checknetsindiffpair=FALSE checkdiffpairvsdiffpair=TRUE checkxsignals=TRUE checkothers=TRUE
MatchedLengths "Schematic Matched Net Lengths_8" [InNet('HEXASPI_IO1')] p23: tolerance=20 checknetsindiffpair=FALSE checkdiffpairvsdiffpair=TRUE checkxsignals=TRUE checkothers=TRUE
MatchedLengths "Schematic Matched Net Lengths_7" [InNet('HEXASPI_IO7')] p24: tolerance=20 checknetsindiffpair=FALSE checkdiffpairvsdiffpair=TRUE checkxsignals=TRUE checkothers=TRUE
MatchedLengths "Schematic Matched Net Lengths_6" [InNet('HEXASPI_DQS0')] p25: tolerance=20 checknetsindiffpair=FALSE checkdiffpairvsdiffpair=TRUE checkxsignals=TRUE checkothers=TRUE
MatchedLengths "Schematic Matched Net Lengths_5" [InNet('OCTOSPI_DQS')] p26: tolerance=20 checknetsindiffpair=FALSE checkdiffpairvsdiffpair=TRUE checkxsignals=TRUE checkothers=TRUE
MatchedLengths "Schematic Matched Net Lengths_4" [InNet('HEXASPI_IO10')] p27: tolerance=20 checknetsindiffpair=FALSE checkdiffpairvsdiffpair=TRUE checkxsignals=TRUE checkothers=TRUE
MatchedLengths "Schematic Matched Net Lengths_3" [InNet('HEXASPI_IO13')] p28: tolerance=20 checknetsindiffpair=FALSE checkdiffpairvsdiffpair=TRUE checkxsignals=TRUE checkothers=TRUE
MatchedLengths "Schematic Matched Net Lengths_2" [InNet('HEXASPI_IO2')] p29: tolerance=20 checknetsindiffpair=FALSE checkdiffpairvsdiffpair=TRUE checkxsignals=TRUE checkothers=TRUE
MatchedLengths "Schematic Matched Net Lengths_1" [InNet('HEXASPI_IO6')] p30: tolerance=20 checknetsindiffpair=FALSE checkdiffpairvsdiffpair=TRUE checkxsignals=TRUE checkothers=TRUE
MatchedLengths "Schematic Matched Net Lengths" [InNet('OCTOSPI_CLK')] p31: tolerance=10 checknetsindiffpair=FALSE checkdiffpairvsdiffpair=TRUE checkxsignals=TRUE checkothers=TRUE
MaxMinImpedance "Schematic Impedance Constraint_10" [InNetClass('OCTOSPI')] p1: minimum=45.00 maximum=55.00
MaxMinImpedance "Schematic Impedance Constraint_24" [InNet('STLK_USB_CN_N')] p2: minimum=85.00 maximum=95.00
MaxMinImpedance "Schematic Impedance Constraint_23" [InNet('STLK_USB_P')] p3: minimum=85.00 maximum=95.00
MaxMinImpedance "Schematic Impedance Constraint_22" [InNet('STLK_USB_N')] p4: minimum=85.00 maximum=95.00
MaxMinImpedance "Schematic Impedance Constraint_21" [InNet('STLK_USB_CN_P')] p5: minimum=85.00 maximum=95.00
MaxMinImpedance "Schematic Impedance Constraint_20" [InNet('HEXASPI_NCS')] p6: minimum=50.00 maximum=60.00
MaxMinImpedance "Schematic Impedance Constraint_19" [InNet('HEXASPI_DQS0')] p7: minimum=50.00 maximum=60.00
MaxMinImpedance "Schematic Impedance Constraint_18" [InNet('HEXASPI_IO2')] p8: minimum=45.00 maximum=55.00
MaxMinImpedance "Schematic Impedance Constraint_17" [InNet('HEXASPI_IO6')] p9: minimum=45.00 maximum=55.00
MaxMinImpedance "Schematic Impedance Constraint_16" [InNet('HEXASPI_IO7')] p10: minimum=45.00 maximum=55.00
MaxMinImpedance "Schematic Impedance Constraint_15" [InNet('HEXASPI_IO0')] p11: minimum=45.00 maximum=55.00
MaxMinImpedance "Schematic Impedance Constraint_14" [InNet('HEXASPI_IO11')] p12: minimum=45.00 maximum=55.00
MaxMinImpedance "Schematic Impedance Constraint_13" [InNet('HEXASPI_IO12')] p13: minimum=45.00 maximum=55.00
MaxMinImpedance "Schematic Impedance Constraint_12" [InNet('HEXASPI_IO13')] p14: minimum=45.00 maximum=55.00
MaxMinImpedance "Schematic Impedance Constraint_11" [InNet('HEXASPI_IO4')] p15: minimum=45.00 maximum=55.00
MaxMinImpedance "Schematic Impedance Constraint_9" [InNet('HEXASPI_IO1')] p16: minimum=45.00 maximum=55.00
MaxMinImpedance "Schematic Impedance Constraint_8" [InNet('HEXASPI_IO15')] p17: minimum=45.00 maximum=55.00
MaxMinImpedance "Schematic Impedance Constraint_7" [InNet('HEXASPI_IO14')] p18: minimum=45.00 maximum=55.00
MaxMinImpedance "Schematic Impedance Constraint_6" [InNet('HEXASPI_IO10')] p19: minimum=45.00 maximum=55.00
MaxMinImpedance "Schematic Impedance Constraint_5" [InNet('HEXASPI_DQS1')] p20: minimum=45.00 maximum=55.00
MaxMinImpedance "Schematic Impedance Constraint_4" [InNet('HEXASPI_IO9')] p21: minimum=45.00 maximum=55.00
MaxMinImpedance "Schematic Impedance Constraint_3" [InNet('HEXASPI_CLK')] p22: minimum=45.00 maximum=55.00
MaxMinImpedance "Schematic Impedance Constraint_2" [InNet('HEXASPI_IO5')] p23: minimum=45.00 maximum=55.00
MaxMinImpedance "Schematic Impedance Constraint_1" [InNet('HEXASPI_IO3')] p24: minimum=45.00 maximum=55.00
MaxMinImpedance "Schematic Impedance Constraint" [InNet('HEXASPI_IO8')] p25: minimum=45.00 maximum=55.00
MinimumSolderMaskSliver [All] p1: minsoldermaskwidth=0.5
PlaneConnect PlaneConnect_1 [WithinRoom('Room_U1')] p1: planeconnectstyle=Relief reliefexpansion=20 reliefentries=4 reliefconductorwidth=10 reliefairgap=6
PlaneConnect [All] p2: planeconnectstyle=Relief reliefexpansion=20 reliefentries=4 reliefconductorwidth=10 reliefairgap=6
PolygonConnect PolygonConnect_via [IsVia] p1: connectstyle=Direct reliefconductorwidth=10 reliefentries=4 polygonreliefangle="90 Angle" airgapwidth=10
PolygonConnect [All] p2: connectstyle=Relief reliefconductorwidth=20 reliefentries=4 polygonreliefangle="90 Angle" airgapwidth=6
RoomDefinition Room_External_SMPS [InComponentClass('Components Class 5')] p1: confinementstyle=ConfineOut formatcopy=TRUE lockcomponents=FALSE outline 1805,3370 1860,3370 1860,3300 1805,3300
RoomDefinition Room_CAMERA [InComponentClass('Components Class 4')] p2: confinementstyle=ConfineIn formatcopy=TRUE lockcomponents=FALSE outline 1751,4010 2420.04,4010 2420.04,3790 1751,3790
RoomDefinition Room_PSRAM [InComponentClass('Components Class 6')] p3: confinementstyle=ConfineOut formatcopy=TRUE lockcomponents=FALSE outline 2800,1780 3065,1780 3065,1441.03 2800,1441.03
RoomDefinition Room_FLASH [InComponentClass('Components Class 3')] p4: confinementstyle=ConfineIn formatcopy=TRUE lockcomponents=FALSE outline 2825.43,2203.46 3065.59,2203.46 3065.59,1884.56 2825.43,1884.56
RoomDefinition Room_STLINK [InComponentClass('Components Class 2')] p5: confinementstyle=ConfineIn formatcopy=TRUE lockcomponents=FALSE outline 4746.89,1226.22 5146.5,1226.22 5146.5,826.62 4746.89,826.62
RoomDefinition Room_MCU [InComponentClass('Components Class 1')] p6: confinementstyle=ConfineIn formatcopy=TRUE lockcomponents=FALSE outline 1747,2088 2525,2088 2525,1312 1747,1312
RoutingLayers "Schematic Routing Layers_1" [InNetClass('HEXASPI')] p1: top layer_v5=TRUE mid layer 1_v5=TRUE mid layer 2_v5=TRUE mid layer 3_v5=TRUE mid layer 4_v5=TRUE bottom layer_v5=FALSE
RoutingLayers "Schematic Routing Layers" [InNetClass('OCTOSPI')] p2: top layer_v5=TRUE mid layer 1_v5=TRUE mid layer 2_v5=TRUE mid layer 3_v5=TRUE mid layer 4_v5=TRUE bottom layer_v5=FALSE
RoutingLayers [All] p3: top layer_v5=TRUE mid layer 1_v5=TRUE mid layer 2_v5=TRUE mid layer 3_v5=TRUE mid layer 4_v5=TRUE bottom layer_v5=TRUE
RoutingVias [All] p1: holewidth=10 width=20 viastyle="Through Hole" minholewidth=4 minwidth=10 maxholewidth=12 maxwidth=24
SilkToSilkClearance [All] p1: silktosilkclearance=0.5
SilkToSolderMaskClearance [IsPad] p1: minsilkscreentomaskgap=0.5 clearancetoexposedcopper=TRUE
SolderMaskExpansion [All] p1: expansion=4 istentingtop=FALSE
Width [All] p1: maxlimit=40 minlimit=4 preferedwidth=5 midlayer2_prefwidth=4 minimp=50.000000 maximp=50.000000 favimp=50.000000
22 further rules are at their usual default settings.

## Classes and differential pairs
net class OCTOSPI: OCTOSPI_CLK OCTOSPI_DQS OCTOSPI_IO0 OCTOSPI_IO1 OCTOSPI_IO2 OCTOSPI_IO3 OCTOSPI_IO4 OCTOSPI_IO5 OCTOSPI_IO6 OCTOSPI_IO7 OCTOSPI_NCS
net class HEXASPI: HEXASPI_CLK HEXASPI_DQS0 HEXASPI_DQS1 HEXASPI_IO0 HEXASPI_IO1 HEXASPI_IO2 HEXASPI_IO3 HEXASPI_IO4 HEXASPI_IO5 HEXASPI_IO6 HEXASPI_IO7 HEXASPI_IO8 HEXASPI_IO9 HEXASPI_IO10 HEXASPI_IO11 HEXASPI_IO12 HEXASPI_IO13 HEXASPI_IO14 HEXASPI_IO15 HEXASPI_NCS
component class U_USB2: C190 C194 C195 CN17 LD8 R201 R211 U47 U48 U49
component class U_USB1_DRP: C151 C184 C185 C186 C187 C196 C197 CN18 LD9 LD10 Q3 Q4 Q5 Q6 R7 R151 R152 R192 R193 R197 R202 R206 R209 R210 R212 R213 R214 R215 R216 R217 R228 R229 SB46 SB47 SB48 U46 U50 U51
component class U_STMOD+: CN4 SB10 SB11 SB12 SB13 SB14 SB15 SB16 SB17 SB18 TP3
component class U_STM32_microcontroller_power: C28 C29 C34 C35 C36 C37 C38 C39 C40 C41 C43 C44 C45 C46 C47 C48 C50 C51 C52 C54 C55 C57 C58 C59 C60 C61 C63 C64 C65 C66 C67 C68 C69 C70 C71 C72 C73 C74 C75 C76 C77 C78 C79 C80 C169 C170 C176 C177 C178 C179 L4 L7 L8 R22 R27 R148 R159 R167 R168 R173 R220 SB4
component class U_STM32_microcontroller_IOs: C153 C155 C174 C175 HW5 R32 R33 R34 R36 R37 R38 R39 R40 R42 R44 R45 R46 R47 R48 R49 R50 R51 R52 R53 R54 R55 R56 R57 R58 R59 R60 R61 R62 R63 R64 R65 R66 R67 R70 R71 R72 R149 R153 R154 R155 R170 R171 SB6 SB7 SB8 SB41 SB42 SB43 SB44 TP8 TP9 TP21 TP22 TP23 TP24 U27 X2 X3
component class U_STLINK_V3EC: C33 C96 C97 C98 C99 C100 C101 C102 C103 C104 C105 C106 C107 C108 C109 C110 C111 C112 C113 C114 C115 C116 C120 C121 C122 C123 C124 C125 C126 C127 C128 C129 C130 C132 C133 CN6 CN9 D1 D2 JP1 LD3 LD4 LNK3 R26 R93 R94 R95 R96 R97 R98 R99 R100 R101 R107 R108 R109 R110 R112 R113 R114 R115 R116 R117 R118 R119 R120 R121 R122 R123 R124 R125 R126 R127 R128 TP2 U15 U16 U17 U18 U19 U20 X1
component class U_SDcard: C85 C86 C145 C146 C152 CN13 D5 D6 R73 R74 R75 R76 R77 R143 R144 R145 R146 R150 U3 U4 U28 U32
component class U_Power: C15 C16 C20 C21 C22 C23 C24 C25 C26 C27 C30 C31 C32 C42 C49 C53 C56 C62 C92 C93 C94 C95 C131 C134 C135 C136 C137 C138 C139 C171 C172 C173 C182 C183 C189 C201 CN2 JP2 L3 L5 L6 LD5 LNK1 LNK2 Q7 R8 R10 R11 R12 R19 R20 R21 R23 R24 R25 R28 R29 R30 R31 R35 R78 R79 R80 R129 R130 R132 R133 R135 R136 R157 R158 R163 R179 R187 R188 R189 R199 R223 TP4 TP10 TP11 TP12 TP13 TP14 TP15 TP16 TP17 TP25 U1 U2 U5 U21 U22 U43 U45
component class U_Peripherals: B1 B2 B4 C198 HW3 HW8 LD1 LD2 Q1 R1 R2 R3 R4 R102 R103 R224 R225 SW1 SW2 U9 U10 U12
component class U_OctoSPI_Flash: C84 C87 C88 C89 C90 C91 D4 R139 R140 R141 R142 SB36 TP6 TP7 U25
component class U_MEMs_microphone: C117 C118 C119 CN5 R104 R105 R106 SB19 TP18 TP19 TP20 U13 U14
component class U_Mechanical: H1 H2 H7 H8 HW1 HW2
component class U_LCD: C81 C82 C83 CN3 H3 H4 H5 H6 R41 R43 R68 R69 SB5 TP1
component class U_HexaSPI_PSRAM: C141 C142 C143 C144 R138 SB35 U26
component class U_External_Debug_Interface: CN1 CN10 R5 SB1 SB2 SB26 SB27 SB28 SB29 SB30 SB54 U23 U24 U52 U53
component class U_Ethernet: C1 C2 C3 C4 C5 C6 C7 C8 C9 C10 C11 C12 C13 C14 C17 C18 C19 C180 C181 C188 C191 C193 CN16 D7 L1 L2 LD7 LE1 R6 R9 R13 R14 R15 R16 R17 R18 R160 R161 R162 R166 R169 R172 R174 R175 R176 R177 R178 R180 R181 R182 R183 R184 R185 R186 R190 R191 R194 R195 R196 R198 R200 R203 R204 R205 R207 R208 R218 R219 SB3 U44 X4
component class U_Camera: C161 C199 C200 CN14 R221 R222 SB45 SB53 U29 U30 U31 U33 U35 U36 U37 U38 U39 U40 U41 U54
component class U_Audio_Codec: C147 C148 C149 C150 C154 C156 C158 C159 C160 C162 C163 C164 C165 C167 C168 CN15 R147 R156 R164 R165 R226 R227 SB37 SB38 SB39 SB40 SB55 SB56 SB57 SB58 SB59 U34 U42
component class U_Arduino_UNO_R3_SMD: C140 CN7 CN8 CN11 CN12 LD6 Q2 R81 R82 R83 R84 R85 R86 R87 R88 R89 R90 R91 R92 R111 R131 R134 R137 SB9 SB20 SB21 SB22 SB23 SB25 SB31 SB32 SB33 SB34 SB49 SB51 TP5 U6 U7 U8
differential pair USB_D1CONN: +USB_D1CONN_P -USB_D1CONN_N
differential pair USB1_CN_HS: +USB1_CN_HS_P -USB1_CN_HS_N
differential pair STLK_USB: +STLK_USB_P -STLK_USB_N
differential pair STLK_USB_CN: +STLK_USB_CN_P -STLK_USB_CN_N
differential pair RJ45_D4: +RJ45_D4_P -RJ45_D4_N
differential pair RJ45_D3: +RJ45_D3_P -RJ45_D3_N
differential pair RJ45_D2: +RJ45_D2_P -RJ45_D2_N
differential pair RJ45_D1: +RJ45_D1_P -RJ45_D1_N
differential pair OTG2_HSD: +OTG2_HSD_P -OTG2_HSD_N
differential pair OTG1_HS: +OTG1_HS_P -OTG1_HS_N

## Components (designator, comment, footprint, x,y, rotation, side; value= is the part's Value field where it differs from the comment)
B1 "SW_BLACK_KSC321JLFS" SWI_C&K_KSC321JLFS_BLACK 5680.01,2170 r0 top value=KSC321JLFS
B2 "SW_BLUE_KSC721JLFS" SWI_C&K_KSC721JLFS_BLUE 5680.01,2670 r0 top value=KSC721JLFS
B4 "SW_BLUE_KSC721JLFS" SWI_C&K_KSC721JLFS_BLUE 5680.01,3170 r0 top value=KSC721JLFS
C1 "Capacitor" C0603 840.01,3200 r0 top locked value=22uF
C2 "Capacitor" C0603 847.64,2937.83 r0 top locked value=22uF
C3 "Capacitor" C0402 945.01,3095 r180 top locked value=100nF
C4 "Capacitor" C0402 946.18,3037.87 r180 top locked value=100nF
C5 "Capacitor" C0402 950,2975 r270 top locked value=100nF
C6 "Capacitor" C0402 955,3160 r90 top locked value=100nF
C7 "Capacitor" C0402 1010,2975 r270 top locked value=100nF
C8 "Capacitor" C0402 1010,3160 r90 top locked value=100nF
C9 "Capacitor" C0603 1095,3450 r270 top locked value=22uF
C10 "Capacitor" C0402 1130.01,2960 r0 top locked value=100nF
C11 "Capacitor" C0402 1130.01,3025 r0 top locked value=100nF
C12 "Capacitor" C0402 1155.01,3110 r0 top locked value=100nF
C13 "Capacitor" C0402 1150,3450 r270 top locked value=100nF
C14 "Capacitor" C0603 1170,3200 r270 top locked value=22uF
C15 "Capacitor" C1206_H1P6 1245,2229 r0 top value=220uF
C16 "Capacitor" C0603 1225.01,1830 r0 top locked value=10uF
C17 "Capacitor" C0402 1205,3450 r270 top locked value=100nF
C18 "Capacitor" C0402 1245.01,3000 r180 top locked value=100nF
C19 "Capacitor" C0603 1240,3085 r90 top locked value=22uF
C20 "Capacitor" C0402 1257,2056 r0 top value=22pF
C21 "Capacitor" C0603 1302,1535 r90 top value=22uF
C22 "Capacitor" C0603 1355,1535 r90 top value=22uF
C23 "Capacitor" C0603 1400.01,2180 r0 top locked value=22uF
C24 "Capacitor" C0402 1400.01,2050 r180 top locked value=1uF
C25 "Capacitor" C0603 1407,1535 r90 top value=22uF
C26 "Capacitor" C0603 1458,1535 r90 top value=22uF
C27 "Capacitor" C0603 1765.01,3475 r180 top locked value=22uF
C28 "Capacitor" C0201_MURATA_GRM033_H0P3 1808.83,1580 r0 top value=100nF
C29 "Capacitor" C0402 1825,1735 r90 top locked value=10uF
C30 "Capacitor" C0402 1710,3265 r270 top value=100pF
C31 "Capacitor" C0603 1895,3334.25 r90 top value=10uF
C32 "Capacitor" C0603 1945,3334.25 r90 top value=10uF
C33 "Capacitor" C0402 4680,1130 r90 top value=10nF
C34 "Capacitor" C0402 1883.2,1600 r270 top locked value=4.7uF
C35 "Capacitor" C0402 1884,1731 r90 top value=10uF
C36 "Capacitor" C0201_MURATA_GRM033_H0P3 1910.01,1445 r180 top locked value=100nF
C37 "Capacitor" C0402 1941,1657 r0 top value=2.2nF
C38 "Capacitor" C0201_MURATA_GRM033_H0P3 1940.52,2007.01 r0 top locked value=1uF
C39 "Capacitor" C0201_MURATA_GRM033_H0P3 1940.52,2037.01 r0 top locked value=100nF
C40 "Capacitor" C0201_MURATA_GRM033_H0P3 1955,1220 r90 top value=100nF
C41 "Capacitor" C0201_MURATA_GRM033_H0P3 1956,1717.83 r90 top value=1uF
C42 "Capacitor" C0603 1907.44,3050 r0 top value=22uF
C43 "Capacitor" C0201_MURATA_GRM033_H0P3 1985,1385 r270 top locked value=1uF
C44 "Capacitor" C0201_MURATA_GRM033_H0P3 1998.01,1856.9 r135 top locked value=1uF
C45 "Capacitor" C0201_MURATA_GRM033_H0P3 1988,1718 r90 top value=1uF
C46 "Capacitor" C0201_MURATA_GRM033_H0P3 2002.1,1915.4 r270 top locked value=100nF
C47 "Capacitor" C0201_MURATA_GRM033_H0P3 2029,1836 r225 top locked value=100nF
C48 "Capacitor" C0201_MURATA_GRM033_H0P3 2018,1718 r90 top value=100nF
C49 "Capacitor" C0603 1907.44,3110 r0 top value=22uF
C50 "Capacitor" C0201_MURATA_GRM033_H0P3 2045,1470 r45 top value=100nF
C51 "Capacitor" C0201_MURATA_GRM033_H0P3 2060.02,1774.98 r225 top locked value=1uF
C52 "Capacitor" C0201_MURATA_GRM033_H0P3 2051,1720 r90 top value=100nF
C53 "Capacitor" C0603 2055,3115 r180 top value=22uF
C54 "Capacitor" C0201_MURATA_GRM033_H0P3 2090.02,1809.98 r225 top locked value=100nF
C55 "Capacitor" C0201_MURATA_GRM033_H0P3 2095.01,1647 r0 top locked value=100nF
C56 "Capacitor" C0603 1907.44,3170 r0 top value=22uF
C57 "Capacitor" C0201_MURATA_GRM033_H0P3 2095,1745 r90 top locked value=1uF
C58 "Capacitor" C0201_MURATA_GRM033_H0P3 2128.21,1630.09 r225 top locked value=100nF
C59 "Capacitor" C0201_MURATA_GRM033_H0P3 2132.81,1585.4 r315 top locked value=100nF
C60 "Capacitor" C0201_MURATA_GRM033_H0P3 2121.48,1747.68 r90 top locked value=1uF
C61 "Capacitor" C0201_MURATA_GRM033_H0P3 2135.02,1849.98 r45 top locked value=1uF
C62 "Capacitor" C0603 1907.44,3230 r0 top value=22uF
C63 "Capacitor" C0201_MURATA_GRM033_H0P3 2150,1750 r90 top locked value=1uF
C64 "Capacitor" C0201_MURATA_GRM033_H0P3 2185.02,1584.98 r225 top locked value=100nF
C65 "Capacitor" C0201_MURATA_GRM033_H0P3 2180,1750 r90 top locked value=1uF
C66 "Capacitor" C0201_MURATA_GRM033_H0P3 2191.52,1655.01 r0 top locked value=100nF
C67 "Capacitor" C0201_MURATA_GRM033_H0P3 2191.69,1688.01 r0 top locked value=100nF
C68 "Capacitor" C0201_MURATA_GRM033_H0P3 2202.53,1852.99 r45 top locked value=1uF
C69 "Capacitor" C0201_MURATA_GRM033_H0P3 2215.02,1804.98 r45 top locked value=1uF
C70 "Capacitor" C0201_MURATA_GRM033_H0P3 2209,1750 r90 top locked value=1uF
C71 "Capacitor" C0201_MURATA_GRM033_H0P3 2250.02,1839.98 r45 top locked value=100nF
C72 "Capacitor" C0201_MURATA_GRM033_H0P3 2254.52,1643.01 r0 top locked value=100nF
C73 "Capacitor" C0201_MURATA_GRM033_H0P3 2255.01,1725 r0 top locked value=100nF
C74 "Capacitor" C0201_MURATA_GRM033_H0P3 2255.01,1765 r0 top locked value=100nF
C75 "Capacitor" C0201_MURATA_GRM033_H0P3 2255.52,1699.01 r0 top locked value=100nF
C76 "Capacitor" C0201_MURATA_GRM033_H0P3 2256.52,1670.01 r0 top locked value=100nF
C77 "Capacitor" C0201_MURATA_GRM033_H0P3 2271,1812 r90 top locked value=100nF
C78 "Capacitor" C0201_MURATA_GRM033_H0P3 2295.02,1754.98 r45 top locked value=100nF
C79 "Capacitor" C0201_MURATA_GRM033_H0P3 2309,1815 r90 top locked value=100nF
C80 "Capacitor" C0201_MURATA_GRM033_H0P3 2331,1815 r90 top locked value=100nF
C81 "Capacitor" C0402 2350,2782.28 r90 top locked value=100nF
C82 "Capacitor" C0805 2420.01,2370 r0 top locked value=10uF
C83 "Capacitor" C0402 2425.01,2440 r180 top locked value=100nF
C84 "Capacitor" C0603 2808,2070 r90 top value=4.7uF
C85 "Capacitor" C0603 2885.01,580 r180 top locked value=4.7uF
C86 "Capacitor" C0402 2890.01,630 r0 top locked value=100nF
C87 "Capacitor" C0402 2885,2055 r90 top locked value=100nF
C88 "Capacitor" C0603 2980.01,1900 r0 top locked value=4.7uF
C89 "Capacitor" C0402 2980.01,1960 r0 top locked value=100nF
C90 "Capacitor" C0402 3020.01,2170 r180 top locked value=100nF
C91 "Capacitor" C0603 3120.01,2160 r180 top locked value=4.7uF
C92 "Capacitor" C0402 3940,1260 r270 top locked value=1uF
C93 "Capacitor" C0603 3995.01,1490 r0 top locked value=22uF
C94 "Capacitor" C0402 3989.5,1327.99 r0 top locked value=1uF
C95 "Capacitor" C0402 3989.5,1367.99 r0 top locked value=1uF
C96 "Capacitor" C0402 4725,1165 r270 top locked value=100nF
C97 "Capacitor" C0402 4766.7,1026.42 r180 top locked value=100nF
C98 "Capacitor" C0402 4770.01,935 r180 top locked value=100nF
C99 "Capacitor" C0402 4780,1165 r270 top locked value=100nF
C100 "Capacitor" C0402 4785,840 r270 top locked value=100nF
C101 "Capacitor" C0402 4840,840 r270 top locked value=100nF
C102 "Capacitor" C0402 4856.69,1051.42 r270 top locked value=100nF
C103 "Capacitor" C0402 4875,1310 r90 top locked value=10nF
C104 "Capacitor" C0402 4880,840 r270 top locked value=100nF
C105 "Capacitor" C0402 4925,1310 r90 top locked value=10nF
C106 "Capacitor" C0402 4935,840 r270 top locked value=100nF
C107 "Capacitor" C0402 4946.69,1213.7 r90 top locked value=100nF
C108 "Capacitor" C0402 4975,840 r270 top locked value=100nF
C109 "Capacitor" C0402 4986.69,1214.13 r90 top locked value=100nF
C110 "Capacitor" C0402 5026.69,1213.7 r90 top locked value=100nF
C111 "Capacitor" C0402 5035,1040 r270 top locked value=100nF
C112 "Capacitor" C0402 5128.99,991.42 r0 top locked value=100nF
C113 "Capacitor" C0402 5128.99,1031.42 r0 top locked value=100nF
C114 "Capacitor" C0402 5128.99,1076.42 r0 top locked value=100nF
C115 "Capacitor" C0402 5130.01,945 r180 top locked value=2.2uF
C116 "Capacitor" C0402 5130.01,1130 r180 top locked value=2.2uF
C117 "Capacitor" C0402 5607.39,761.51 r180 bottom value=100nF
C118 "Capacitor" C0402 5607.39,801.51 r180 bottom value=1uF
C119 "Capacitor" C0402 5607.39,876.51 r180 bottom value=100nF
C120 "Capacitor" C0402 5495,1295 r180 bottom value=100pF
C121 "Capacitor" C0402 5236.7,1116.42 r180 bottom locked value=2.2uF
C122 "Capacitor" C0402 5235.01,1020 r0 bottom locked value=20pF
C123 "Capacitor" C0603 4885.01,225 r0 bottom locked value=10uF
C124 "Capacitor" C0603 4885.51,1517.01 r90 bottom locked value=10uF
C125 "Capacitor" C0402 4890,470 r270 bottom locked value=100nF
C126 "Capacitor" C0805 4785.52,1502.01 r180 bottom locked value=2.2uF
C127 "Capacitor" C0402 4686.69,961.42 r270 bottom locked value=5.6pF
C128 "Capacitor" C0402 4686.69,1038.7 r270 bottom locked value=5.6pF
C129 "Capacitor" C0603 4670,335 r270 bottom locked value=10uF
C130 "Capacitor" C0402 4656.7,1116.42 r0 bottom locked value=100nF
C131 "Capacitor" C0805 4615,2604.99 r270 bottom locked value=10uF
C132 "Capacitor" C0402 4630,470 r270 bottom locked value=100nF
C133 "Capacitor" C0402 4510,470 r270 bottom locked value=10nF
C134 "Capacitor" C0805 4233.03,2420.16 r270 bottom locked value=10uF
C135 "Capacitor" C0603 4195,1145 r270 bottom locked value=22uF
C136 "Capacitor" C0603 4125,1145 r270 bottom locked value=22uF
C137 "Capacitor" C0603 4020,1005 r270 bottom locked value=10uF
C138 "Capacitor" C1206_H1P6 3787,830 r0 bottom value=220uF
C139 "Capacitor" C0402 3790.68,922.13 r0 bottom locked value=1uF
C140 "Capacitor" C0402 3630.52,3347.01 r180 bottom locked value=100nF
C141 "Capacitor" C0603 3160.51,1589.01 r270 bottom locked value=4.7uF
C142 "Capacitor" C0402 3115,1590 r270 bottom locked value=100nF
C143 "Capacitor" C0603 2875.52,1349.01 r0 bottom locked value=4.7uF
C144 "Capacitor" C0402 2875.52,1402.01 r0 bottom locked value=100nF
C145 "Capacitor" C0402 2345.01,890 r180 bottom locked value=1uF
C146 "Capacitor" C0603 2277.01,799.49 r270 bottom locked value=10uF
C147 "Capacitor" C0603 2155,592.56 r270 bottom value=4.7uF
C148 "Capacitor" C0603 1945.65,227.26 r90 bottom value=2.2uF
C149 "Capacitor" C0402 1995,232.28 r90 bottom value=100nF
C150 "Capacitor" C0603 2336.61,487.97 r180 bottom value=4.7uF
C151 "Capacitor" C0402 2142.7,2395 r180 bottom locked value=10pF
C152 "Capacitor" C0402 2145,1000 r270 bottom locked value=100nF
C153 "Capacitor" C0402 2115.01,1195 r180 bottom locked value=8.2pF
C154 "Capacitor" C0603 2197.56,440 r0 bottom value=1uF
C155 "Capacitor" C0402 2040.01,1195 r0 bottom locked value=8.2pF
C156 "Capacitor" C0603 2197.56,495 r0 bottom value=1uF
C158 "Capacitor" C0603 1995,592.56 r90 bottom value=4.7uF
C159 "Capacitor" C0402 2055,229.57 r90 bottom value=100nF
C160 "Capacitor" C0603 1865,300 r0 bottom value=2.2uF
C161 "Capacitor" C0402 1860,3930 r90 bottom value=1uF
C162 "Capacitor" C0402 1940,577.72 r270 bottom value=100nF
C163 "Capacitor" C0603 1825,360 r180 bottom value=2.2uF
C164 "Capacitor" C0402 1812.72,550 r180 bottom value=100nF
C165 "Capacitor" C0402 1825,465 r180 bottom value=100nF
C167 "Capacitor" C0603 1825,415 r180 bottom value=2.2uF
C168 "Capacitor" C0603 2050,590 r270 bottom value=4.7uF
C169 "Capacitor" C0201_MURATA_GRM033_H0P3 1727,1580.59 r90 bottom value=100nF
C170 "Capacitor" C0603 1690.01,1875 r0 bottom locked value=22uF
C171 "Capacitor" C0402 1710,960 r90 bottom locked value=1uF
C172 "Capacitor" C0402 1660,960 r90 bottom locked value=1uF
C173 "Capacitor" C0402 1595.01,900 r180 bottom locked value=1uF
C174 "Capacitor" C0402 1610.39,1418.69 r90 bottom locked value=3.3pF
C175 "Capacitor" C0402 1610.39,1508.69 r270 bottom locked value=3.3pF
C176 "Capacitor" C0603 1590.51,1777.01 r90 bottom locked value=22uF
C177 "Capacitor" C0603 1590.51,1912.01 r270 bottom locked value=22uF
C178 "Capacitor" C0603 1530.51,1777.01 r90 bottom locked value=22uF
C179 "Capacitor" C0603 1530.51,1912.01 r270 bottom locked value=22uF
C180 "Capacitor" C0402 1320,2730 r90 bottom locked value=100nF
C181 "Capacitor" C0603 1270,2725 r90 bottom locked value=22uF
C182 "Capacitor" C0603 1180.01,2385 r180 bottom locked value=22uF
C183 "Capacitor" C0603 1180,2330 r180 bottom locked value=10uF
C184 "Capacitor" C0402 1160,1490 r270 bottom locked value=10nF
C185 "Capacitor" C0603 1130.01,1075 r0 bottom locked value=100nF
C186 "Capacitor" C0402 1130.01,1025 r180 bottom locked value=330pF
C187 "Capacitor" C0402 1130.01,1129 r180 bottom value=330pF
C188 "Capacitor" C0402 1010.01,2795 r180 bottom locked value=6.8pF
C189 "Capacitor" C0603 995.01,2340 r0 bottom locked value=10uF
C190 "Capacitor" C0402 998,1825.51 r180 bottom locked value=100nF
C191 "Capacitor" C0402 935.01,2795 r0 bottom locked value=6.8pF
C193 "Capacitor" C0402 755,3025 r270 bottom locked value=100nF
C194 "Capacitor" C0402 745,1845 r90 bottom locked value=100nF
C195 "Capacitor" C1206_H1P6 610,1850 r270 bottom locked value=220uF
C196 "Capacitor" C0805_H0P6 585,1410 r270 bottom locked value=1nF
C197 "Capacitor" C0805 460.19,1169.25 r180 bottom value=2.2uF
C198 "Capacitor" C0402 1905,1140 r270 bottom value=10nF
C199 "Capacitor" C0805 2750,3608.46 r270 bottom value=10uF
C200 "Capacitor" C0805 2620,3608.46 r270 bottom value=10uF
C201 "Capacitor" C1206_H1P6 4255,719 r180 bottom value=220uF
CN1 "Tag-10-C" CON_TAG-C_TC2050-IDC-NL 270.02,3690 r270 top locked value="Header 5x2"
CN2 "Header 7x2" CON_SAMTEC_TSW-107-07-X-D 1035,4130 r0 top locked value="Jumper_Header 7x2"
CN3 "Socket 25x2" CON_SAMTEC_FLE-125-01-G-DV 2952.87,2603.66 r180 top locked
CN4 "Socket 10X2 STMod+" CON_SAMTEC_SQT-110-01-F-D-RA__STMOD+ 4664.38,3991.34 r180 top locked value="Socket 10X2"
CN5 "Socket 10x2" CON_FCI_20021311-XXX20XXLF 5763.72,720.9 r90 top locked
CN6 "USB_TYPE_C_Receptacle" CON_USB-TYPEC_AMPHENOL_12401826E412A 5611.93,1211.18 r270 bottom locked value=USB_C_12401826E412A
CN7 "Socket 6x1" CON_SAMTEC_SSW-106-22-X-S-VS 5305,1985 r90 bottom
CN8 "Socket 8x1" CON_SAMTEC_SSW-108-22-X-S-VS 5305,2785 r90 bottom
CN9 "Header 4x1" CON_SAMTEC_TSW-104-07-G-S 5170.51,627.01 r0 bottom locked
CN10 "Header 10x2" CON_SAMTEC_FTSH-110-01-L-DV 3705.65,372.01 r270 bottom locked
CN11 "Socket 8x1" CON_SAMTEC_SSW-108-22-X-S-VS 3405,2085 r270 bottom locked
CN12 "Socket 10x1" CON_SAMTEC_SSW-110-22-X-S-VS 3405,3045 r270 bottom locked
CN13 "microSD-PJS008-2003" CON_MICROSD_YAMAICHI_PJS008-2003-1 2954.3,-11.82 r270 bottom locked value=uSD-Card_PJS008-2003-1
CN14 "2-1734592-2" CON_TE-CONNECTIVITY_2-1734592-2_INV 2126.3,4097.64 r0 bottom value=FFC/FPPC_2-1734592-2
CN15 "Jack_PJ3028B-3_4P" CON_PHONE-JACK-3P5_HY_PJ3028B 1305.84,10.32 r90 bottom locked value="Jack_ Socket-Stereo_PJ-3028B-4P"
CN16 "​New part for use of led pulled down on pin 13/14 , schematic more lisible." CON_RJ45_YD_48F-01GYDXNL_LED-P 1.15,3016.8 r90 bottom locked value=RJ45_48F-01GYDXNL
CN17 "USB_TypeA_Receptacle_67643-3911" CON_USB-TYPEA_MOLEX_67643-3911_H7P73 -51.42,2010.63 r90 bottom locked value=USB_A_67643-3911
CN18 "USB_TYPE_C_Receptacle" CON_USB-TYPEC_AMPHENOL_12401826E412A 289.42,1083.93 r90 bottom locked value=USB_C_12401826E412A
D1 "SCHOTTKY_1A_2K" DIO_SOD323_1A_2K 4670.51,1547.01 r270 bottom locked value=BAT20JFILM
D2 "SCHOTTKY_1A_2K" DIO_SOD323_1A_2K 4605.51,1547.01 r270 bottom locked value=BAT20JFILM
D4 "BAT60JFILM" DIO_SOD323 2900.52,1832.01 r180 bottom locked
D5 "BAT60JFILM" DIO_SOD323 2562.01,799.49 r270 bottom locked
D6 "BAT60JFILM" DIO_SOD323 2492.01,799.49 r270 bottom locked
D7 "BAT60JFILM" DIO_SOD323 835.01,3255 r180 bottom locked
H1 "POSITION HOLE" PTH_350_700 200,200 r180 top locked value=N/A
H2 "POSITION HOLE" PTH_350_700 200,4130.71 r180 top locked value=N/A
H3 "POSITION HOLE" PTH_450_900 659.96,243.35 r0 top locked value=N/A
H4 "POSITION HOLE" PTH_450_900 659.96,3611.06 r0 top locked value=N/A
H5 "POSITION HOLE" PTH_450_900 5245.79,243.35 r0 top locked value=N/A
H6 "POSITION HOLE" PTH_450_900 5245.79,3611.06 r0 top locked value=N/A
H7 "POSITION HOLE" PTH_350_700 5705.51,200 r180 top locked value=N/A
H8 "POSITION HOLE" PTH_350_700 5705.51,4130.71 r180 top locked value=N/A
HW1 "STICKER_PRODUCT" STICKER_PRODUCT_25X9 3460,4105 r0 top locked value=N/A
HW2 "STICKER_BOARD" STICKER_BOARD_25X9 3460,4105 r180 bottom locked value=N/A
JP1 "Jumper_Header 2x1" CON_SAMTEC_TSW-102-07-G-S 4595,620 r0 bottom locked value="Header 2x1"
JP2 "Jumper_Header 3x2" CON_SAMTEC_TSM-103-01-X-DV 4245.01,375 r270 bottom locked value=Jumper_Header_3x2
L1 "BEAD" FIL_0603_H0P65 840.01,3260 r180 top locked value="100R @ 100MHz"
L2 "BEAD" FIL_0603_H0P65 975.01,3405 r180 top locked value="100R @ 100MHz"
L3 "Inductor" IND_4025_WURTH_74404043022A 1370,1690 r270 top locked value=2.2uH
L4 "Inductor" L0603 1760,1735 r90 top locked value=2.2nH
L5 "Inductor" IND_MURATA_DFE201612P 2020,3302.76 r270 top value=240nH
L6 "Inductor" IND_4025_WURTH_74404043022A 4175,990 r90 bottom locked value=2.2uH
L7 "Inductor" IND_MURATA_DFE201612P 1694,1735 r0 bottom value=1.0uH
L8 "Inductor" IND_0603_LSMCA_H1P0 1682,1603 r270 bottom value="18R @ 100MHz"
LD1 "LED_green" LED_0603_OSRAM_LG-Q396-PS-35_GREEN_1A2K_H0P4 90.01,735 r180 top locked value=Green
LD2 "LED_red" LED_0603_VISHAY_VLMS1300-GS08_RED_1A2K_H0P8 211.66,735 r0 top locked value=Red
LD3 "LED_BICOLOR" LED_BI-GR_WE-150141SV73110 5710.01,1530 r90 top locked value=Red/Green
LD4 "LED_BICOLOR" LED_BI-GR_WE-150141SV73110 5710.01,1695 r90 top locked value=Red/Green
LD5 "LED_green" LED_0603_OSRAM_LG-Q396-PS-35_GREEN_1A2K_H0P4 4376.02,606.38 r0 bottom locked value=Green
LD6 "LED_green" LED_0603_OSRAM_LG-Q396-PS-35_GREEN_1A2K_H0P4 3930.01,3015 r0 bottom locked value=Green
LD7 "LED_green" LED_0603_OSRAM_LG-Q396-PS-35_GREEN_1A2K_H0P4 1145.01,2760 r0 bottom locked value=Green
LD8 "LED_red" LED_0603_VISHAY_VLMS1300-GS08_RED_1A2K_H0P8 980,1950 r180 bottom locked value=Red
LD9 "LED_green" LED_0603_OSRAM_LG-Q396-PS-35_GREEN_1A2K_H0P4 484,1495.94 r90 bottom locked value=Green
LD10 "LED_red" LED_0603_VISHAY_VLMS1300-GS08_RED_1A2K_H0P8 260.01,1610 r0 bottom locked value=Red
LE1 "Inductor" L1210_LQH 1325,2870 r270 bottom locked value=4.7uH
LNK1 "link_200" LINK200 1412,2300 r180 top locked
LNK2 "link_200" LINK200 1740,3585 r180 top
LNK3 "link_200" LINK200 4690,1315 r180 bottom locked
Q1 "9013-SOT23" NPN_SOT23 200.52,587.01 r90 top locked value=BSR14
Q2 "BSN20" MOS_SOT23 3922.02,3114.49 r90 bottom locked value=BSN20BK
Q3 "STL40DN3LLH5" PowerFLAT_5x6 996.01,1479.49 r0 bottom locked
Q4 "STL40DN3LLH5" PowerFLAT_5x6 725,1479.99 r0 bottom locked
Q5 "9013-SOT23" NPN_SOT23 379.01,1495.94 r180 bottom locked value=BSR14
Q6 "9013-SOT23" NPN_SOT23 150.01,1495 r180 bottom locked value=BSR14
Q7 "MOSFET_N-CHANNEL" MOS_SC89-3L 1666.9,3180.65 r0 top value=Si1062X
R1 "Resistor" R0402 77.02,589.49 r180 top locked value=330R
R2 "Resistor" R0402 315.01,735 r180 top locked value=680R
R3 "Resistor" R0402 310,585 r270 top locked value=100K
R4 "Resistor" R0402 365,585 r90 top locked value=47K
R5 "Resistor" R0402 460.01,3845 r0 top locked value=10K
R6 "Resistor" R0603 847.64,2882.83 r180 top locked value=0R
R7 "Resistor" R0603 986.01,1415 r0 top locked value=22mR
R8 "Resistor" R0402 1220,1940 r90 top locked value=330R
R9 "Resistor" R0603 1240,3200 r90 top locked value=0R
R10 "Resistor" R0402 1257,2094 r0 top value=24K
R11 "Resistor" R0402 1257,2136 r180 top value=30K
R12 "Resistor" R0402 1315,2075 r270 top locked value=0R
R13 "Resistor" R0402 1335,3000 r180 top locked value=4K7
R14 "Resistor" R0402 1335,3040 r180 top locked value=4K7
R15 "Resistor" R0402 1335,3080 r180 top locked value=4K7
R16 "Resistor" R0402 1335,3120 r180 top locked value=4K7
R17 "Resistor" R0402 1335,3160 r180 top locked value=4K7
R18 "Resistor" R0402 1335,3200 r180 top locked value=4K7
R19 "Resistor" R0603 1400.01,2125 r180 top locked value=0R
R20 "Resistor" R0603 1400.01,2235 r180 top locked value=330mR
R21 "Resistor" R0603 1519.44,1616 r0 top value=0R
R22 "Resistor" R0603 1685,1900 r270 top locked value=0R
R23 "Resistor" R0603 1765.01,3410 r0 top locked value=0R
R24 "Resistor" R0603 1765.01,3530 r0 top locked value=330mR
R25 "Resistor" R0402 1750,3345 r0 top value=0R
R26 "Resistor" R0402 4682.28,795 r0 top value=10K
R27 "Resistor" R0603 1940.51,2137.01 r270 top locked value=0R
R28 "Resistor" R0402 1665,3265 r270 top value=56K
R29 "Resistor" R0402 1755,3265 r90 top value=160K
R30 "Resistor" R0603 2090,2970 r270 top value=0R
R31 "Resistor" R0603 2055,3050 r0 top value=0R
R32 "Resistor" R0402 2045,1250 r270 top locked value=200R
R33 "Resistor" R0402 2055,2130 r90 top locked value=200R
R34 "Resistor" R0402 2100,1250 r270 top locked value=200R
R35 "Resistor" R0603 2055,3180 r0 top value=50mR
R36 "Resistor" R0402 2245,1410 r90 top locked value=1K5
R37 "Resistor" R0402 2280,2140 r270 top locked value=0R
R38 "Resistor" R0402 2305,1410 r90 top locked value=1K5
R39 "Resistor" R0402 2320,2140 r270 top locked value=0R
R40 "Resistor" R0402 2360,2140 r270 top locked value=0R
R41 "Resistor" R0603 2370,2285 r90 top locked value=0R
R42 "Resistor" R0402 2420.01,2155 r180 top locked value=0R
R43 "Resistor" R0603 2465,2285 r90 top locked value=0R
R44 "Resistor" R0402 2500.01,1565 r180 top locked value=0R
R45 "Resistor" R0402 2500.01,1610 r180 top locked value=0R
R46 "Resistor" R0402 2500.01,1655 r180 top locked value=0R
R47 "Resistor" R0402 2500.01,1700 r180 top locked value=0R
R48 "Resistor" R0402 2500.01,1745 r180 top locked value=0R
R49 "Resistor" R0402 2500.01,1790 r180 top locked value=0R
R50 "Resistor" R0402 2500.01,1835 r180 top locked value=0R
R51 "Resistor" R0402 2500.01,1880 r180 top locked value=0R
R52 "Resistor" R0402 2515.01,2155 r180 top locked value=0R
R53 "Resistor" R0402 2590.01,1470 r180 top locked value=0R
R54 "Resistor" R0402 2590.01,1515 r180 top locked value=0R
R55 "Resistor" R0402 2590.01,1565 r180 top locked value=0R
R56 "Resistor" R0402 2590.01,1610 r180 top locked value=0R
R57 "Resistor" R0402 2590.01,1655 r180 top locked value=0R
R58 "Resistor" R0402 2590.01,1700 r180 top locked value=0R
R59 "Resistor" R0402 2590.01,1745 r180 top locked value=0R
R60 "Resistor" R0402 2590.01,1790 r180 top locked value=0R
R61 "Resistor" R0402 2590.01,1835 r180 top locked value=0R
R62 "Resistor" R0402 2590.01,1880 r180 top locked value=0R
R63 "Resistor" R0402 2590.01,1920 r180 top locked value=0R
R64 "Resistor" R0402 2590.01,1965 r180 top locked value=0R
R65 "Resistor" R0402 2593.01,2035 r180 top locked value=0R
R66 "Resistor" R0402 2593.01,2075 r180 top locked value=0R
R67 "Resistor" R0402 2593.01,2125 r180 top locked value=0R
R68 "Resistor" R0402 2600,2785 r90 top locked value=0R
R69 "Resistor" R0402 2655,2785 r90 top locked value=0R
R70 "Resistor" R0402 2690.01,1970 r180 top locked value=0R
R71 "Resistor" R0402 2690.01,2015 r180 top locked value=0R
R72 "Resistor" R0402 2690.01,2060 r180 top locked value=0R
R73 "Resistor" R0402 2740,822.28 r90 top value=47K
R74 "Resistor" R0402 2795,822.28 r90 top value=47K
R75 "Resistor" R0402 2960,822 r90 top value=10K
R76 "Resistor" R0402 3002,821 r90 top value=47K
R77 "Resistor" R0402 3049,821 r90 top value=47K
R78 "Resistor" R0603 3885.01,1490 r180 top locked value=0R
R79 "Resistor" R0603 3994.5,1427.99 r180 top locked value=0R
R80 "Resistor" R0603 3995.01,1555 r180 top locked value=750mR
R81 "Resistor" R0402 4143.52,3012.01 r180 top locked value=470K
R82 "Resistor" R0402 4143.52,3058.01 r180 top locked value=560K
R83 "Resistor" R0402 4210,3210 r90 top locked value=560K
R84 "Resistor" R0402 4255,3210 r90 top locked value=470K
R85 "Resistor" R0402 4415.01,3015 r180 top locked value=470K
R86 "Resistor" R0402 4415.01,3060 r180 top locked value=560K
R87 "Resistor" R0402 4480,3210 r90 top locked value=560K
R88 "Resistor" R0402 4530,3210 r90 top locked value=470K
R89 "Resistor" R0402 4690.01,3015 r180 top locked value=470K
R90 "Resistor" R0402 4690.01,3060 r180 top locked value=560K
R91 "Resistor" R0402 4750,3210 r90 top locked value=560K
R92 "Resistor" R0402 4795,3210 r90 top locked value=470K
R93 "Resistor" R0402 4855,980 r90 top locked value=10K
R94 "Resistor" R0402 5066.69,1213.7 r90 top locked value=33R
R95 "Resistor" R0402 5111.69,1213.7 r90 top locked value=33R
R96 "Resistor" R0402 5375.01,1300 r0 top locked value=100K
R97 "Resistor" R0402 5375.52,1127.01 r0 top locked value=100K
R98 "Resistor" R0402 5567.73,1500 r180 top locked value=1K
R99 "Resistor" R0402 5567.73,1560 r180 top locked value=330R
R100 "Resistor" R0402 5567.73,1665 r180 top locked value=1K
R101 "Resistor" R0402 5567.73,1725 r0 top locked value=330R
R102 "Resistor" R0402 5670,3520 r180 top locked value=10K
R103 "Resistor" R0402 5670,3840 r180 top locked value=10K
R104 "Resistor" R0402 5607.39,916.51 r0 bottom value=0R
R105 "Resistor" R0402 5530.97,723 r0 bottom locked value=10K
R106 "Resistor" R0402 5398.68,893 r90 bottom locked value=10K
R107 "Resistor" R0402 5375.52,1127.01 r180 bottom locked value=5K1
R108 "Resistor" R0402 5375.01,1300 r180 bottom locked value=5K1
R109 "Resistor" R0402 5236.7,1071.42 r0 bottom locked value=3K
R110 "Resistor" R0402 5235.01,975 r0 bottom locked value=100R
R111 "Resistor" R0402 5110.01,3135 r180 bottom locked value=1K
R112 "Resistor" R0402 4971.69,743.7 r270 bottom locked value=0R
R113 "Resistor" R0402 4926.69,1306.42 r90 bottom locked value=5K1
R114 "Resistor" R0402 4910,745 r270 bottom locked value=33R
R115 "Resistor" R0402 4876.69,1306.42 r90 bottom locked value=10K
R116 "Resistor" R0402 4860,745 r270 bottom locked value=0R
R117 "Resistor" R0402 4831.69,1306.42 r90 bottom locked value=0R
R118 "Resistor" R0402 4820,470 r270 bottom locked value=100K
R119 "Resistor" R0402 4786.69,1306.42 r90 bottom locked value=10K
R120 "Resistor" R0402 4775,215 r90 bottom locked value=100K
R121 "Resistor" R0402 4741.69,1306.42 r90 bottom locked value=10K
R122 "Resistor" R0402 4656.7,1166.42 r180 bottom locked value=33R
R123 "Resistor" R0402 4645,160 r180 bottom locked value=3K9
R124 "Resistor" R0402 4645,210 r0 bottom locked value=3K
R125 "Resistor" R0402 4570,470 r270 bottom locked value=100K
R126 "Resistor" R0402 4555.01,185 r180 bottom locked value=1K3
R127 "Resistor" R0402 4555.01,235 r180 bottom locked value=1K8
R128 "Resistor" R0402 4555.01,280 r180 bottom locked value=3K9
R129 "Resistor" R0603 4254.66,606.64 r0 bottom locked value=820R
R130 "Resistor" R0603 3936.56,822 r180 bottom value=0R
R131 "Resistor" R0402 3930.52,2957.01 r0 bottom locked value=330R
R132 "Resistor" R0402 3920.01,1045 r180 bottom locked value=560R
R133 "Resistor" R0402 3807.95,997.13 r270 bottom locked value=24K
R134 "Resistor" R0402 3787.01,3109.49 r270 bottom locked value=1M
R135 "Resistor" R0402 3755,1000 r90 bottom locked value=75K
R136 "Resistor" R0603 3653,1000 r270 bottom value=0R
R137 "Resistor" R0402 3630.52,3297.01 r0 bottom locked value=0R
R138 "Resistor" R0402 3135.01,1680 r0 bottom locked value=10K
R139 "Resistor" R0402 3135.51,1982.01 r90 bottom locked value=10K
R140 "Resistor" R0402 3022.81,1830.27 r0 bottom locked value=10K
R141 "Resistor" R0402 2780,2010 r270 bottom locked value=0R
R142 "Resistor" R0402 2780,2085 r90 bottom locked value=10K
R143 "Resistor" R0402 2468.3,414.1 r180 bottom value=10K
R144 "Resistor" R0402 2427.01,799.49 r90 bottom locked value=10K
R145 "Resistor" R0603 2350.01,945 r180 bottom locked value=0R
R146 "Resistor" R0402 2342.02,704.49 r180 bottom locked value=0R
R147 "Resistor" R0603 2200,235 r270 bottom value=0R
R148 "Resistor" R0805 1900,1025 r90 bottom value=0R
R149 "Resistor" R0402 2210,1250 r90 bottom locked value=1K5
R150 "Resistor" R0402 2185,1000 r270 bottom locked value=100K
